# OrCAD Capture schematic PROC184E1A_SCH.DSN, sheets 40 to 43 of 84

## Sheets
40 44. MICRO SDCARD INTERFACE: size C; title: Micro SD CARD INTERFACE; note: PROC184_SCH
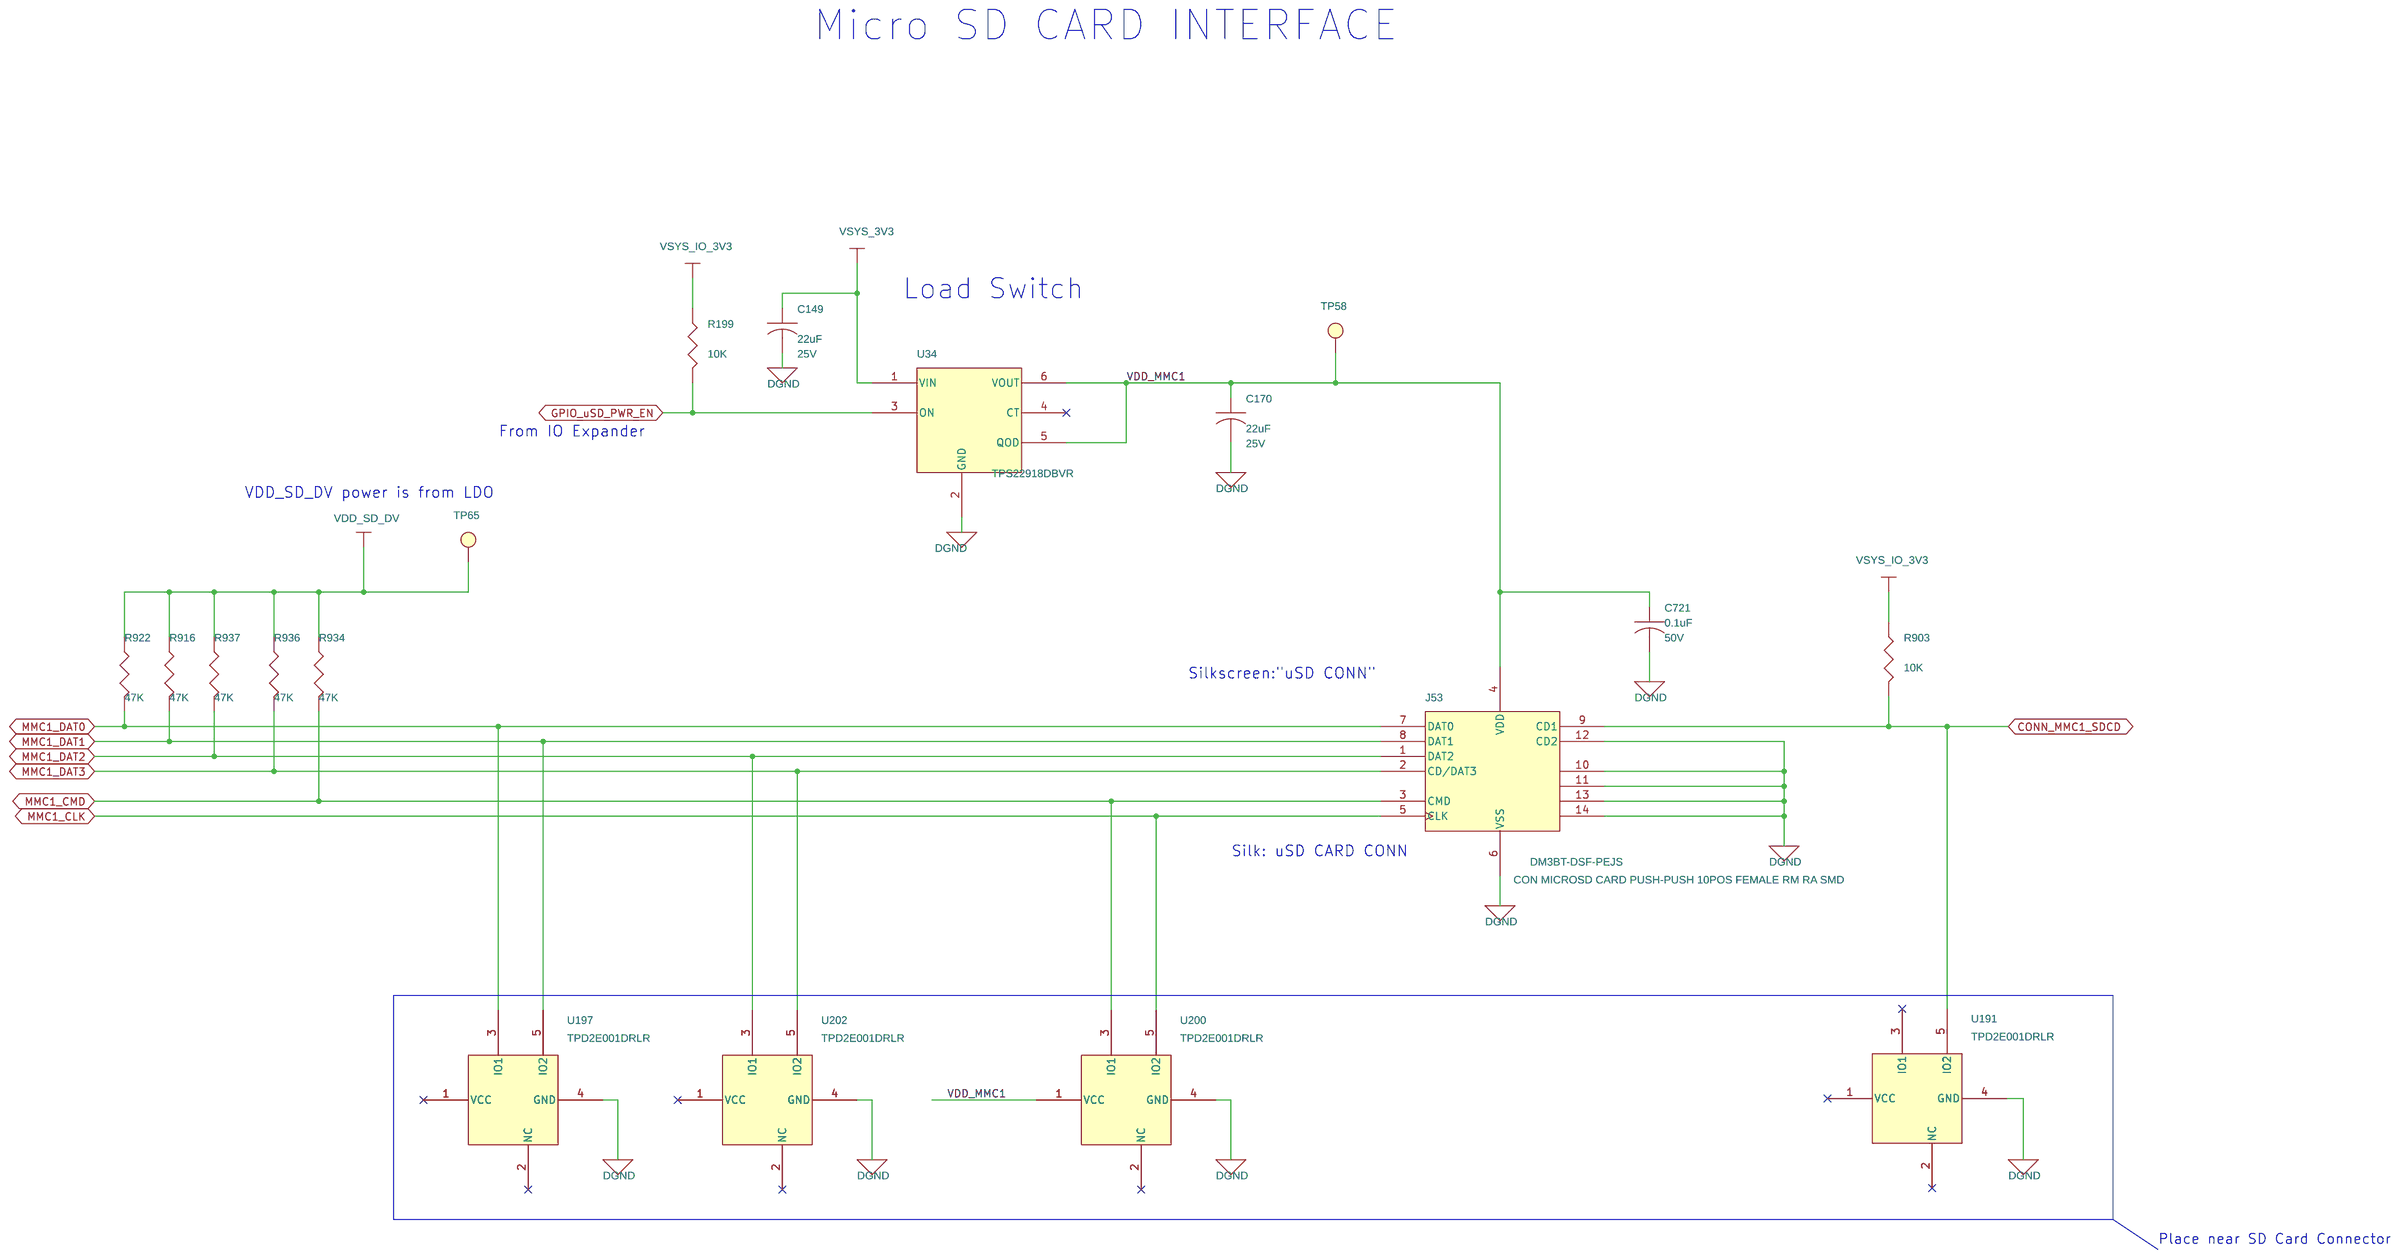
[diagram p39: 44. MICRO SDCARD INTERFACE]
41 45. eMMC FLASH: size C; title: eMMC FLASH; note: PROC184_SCH
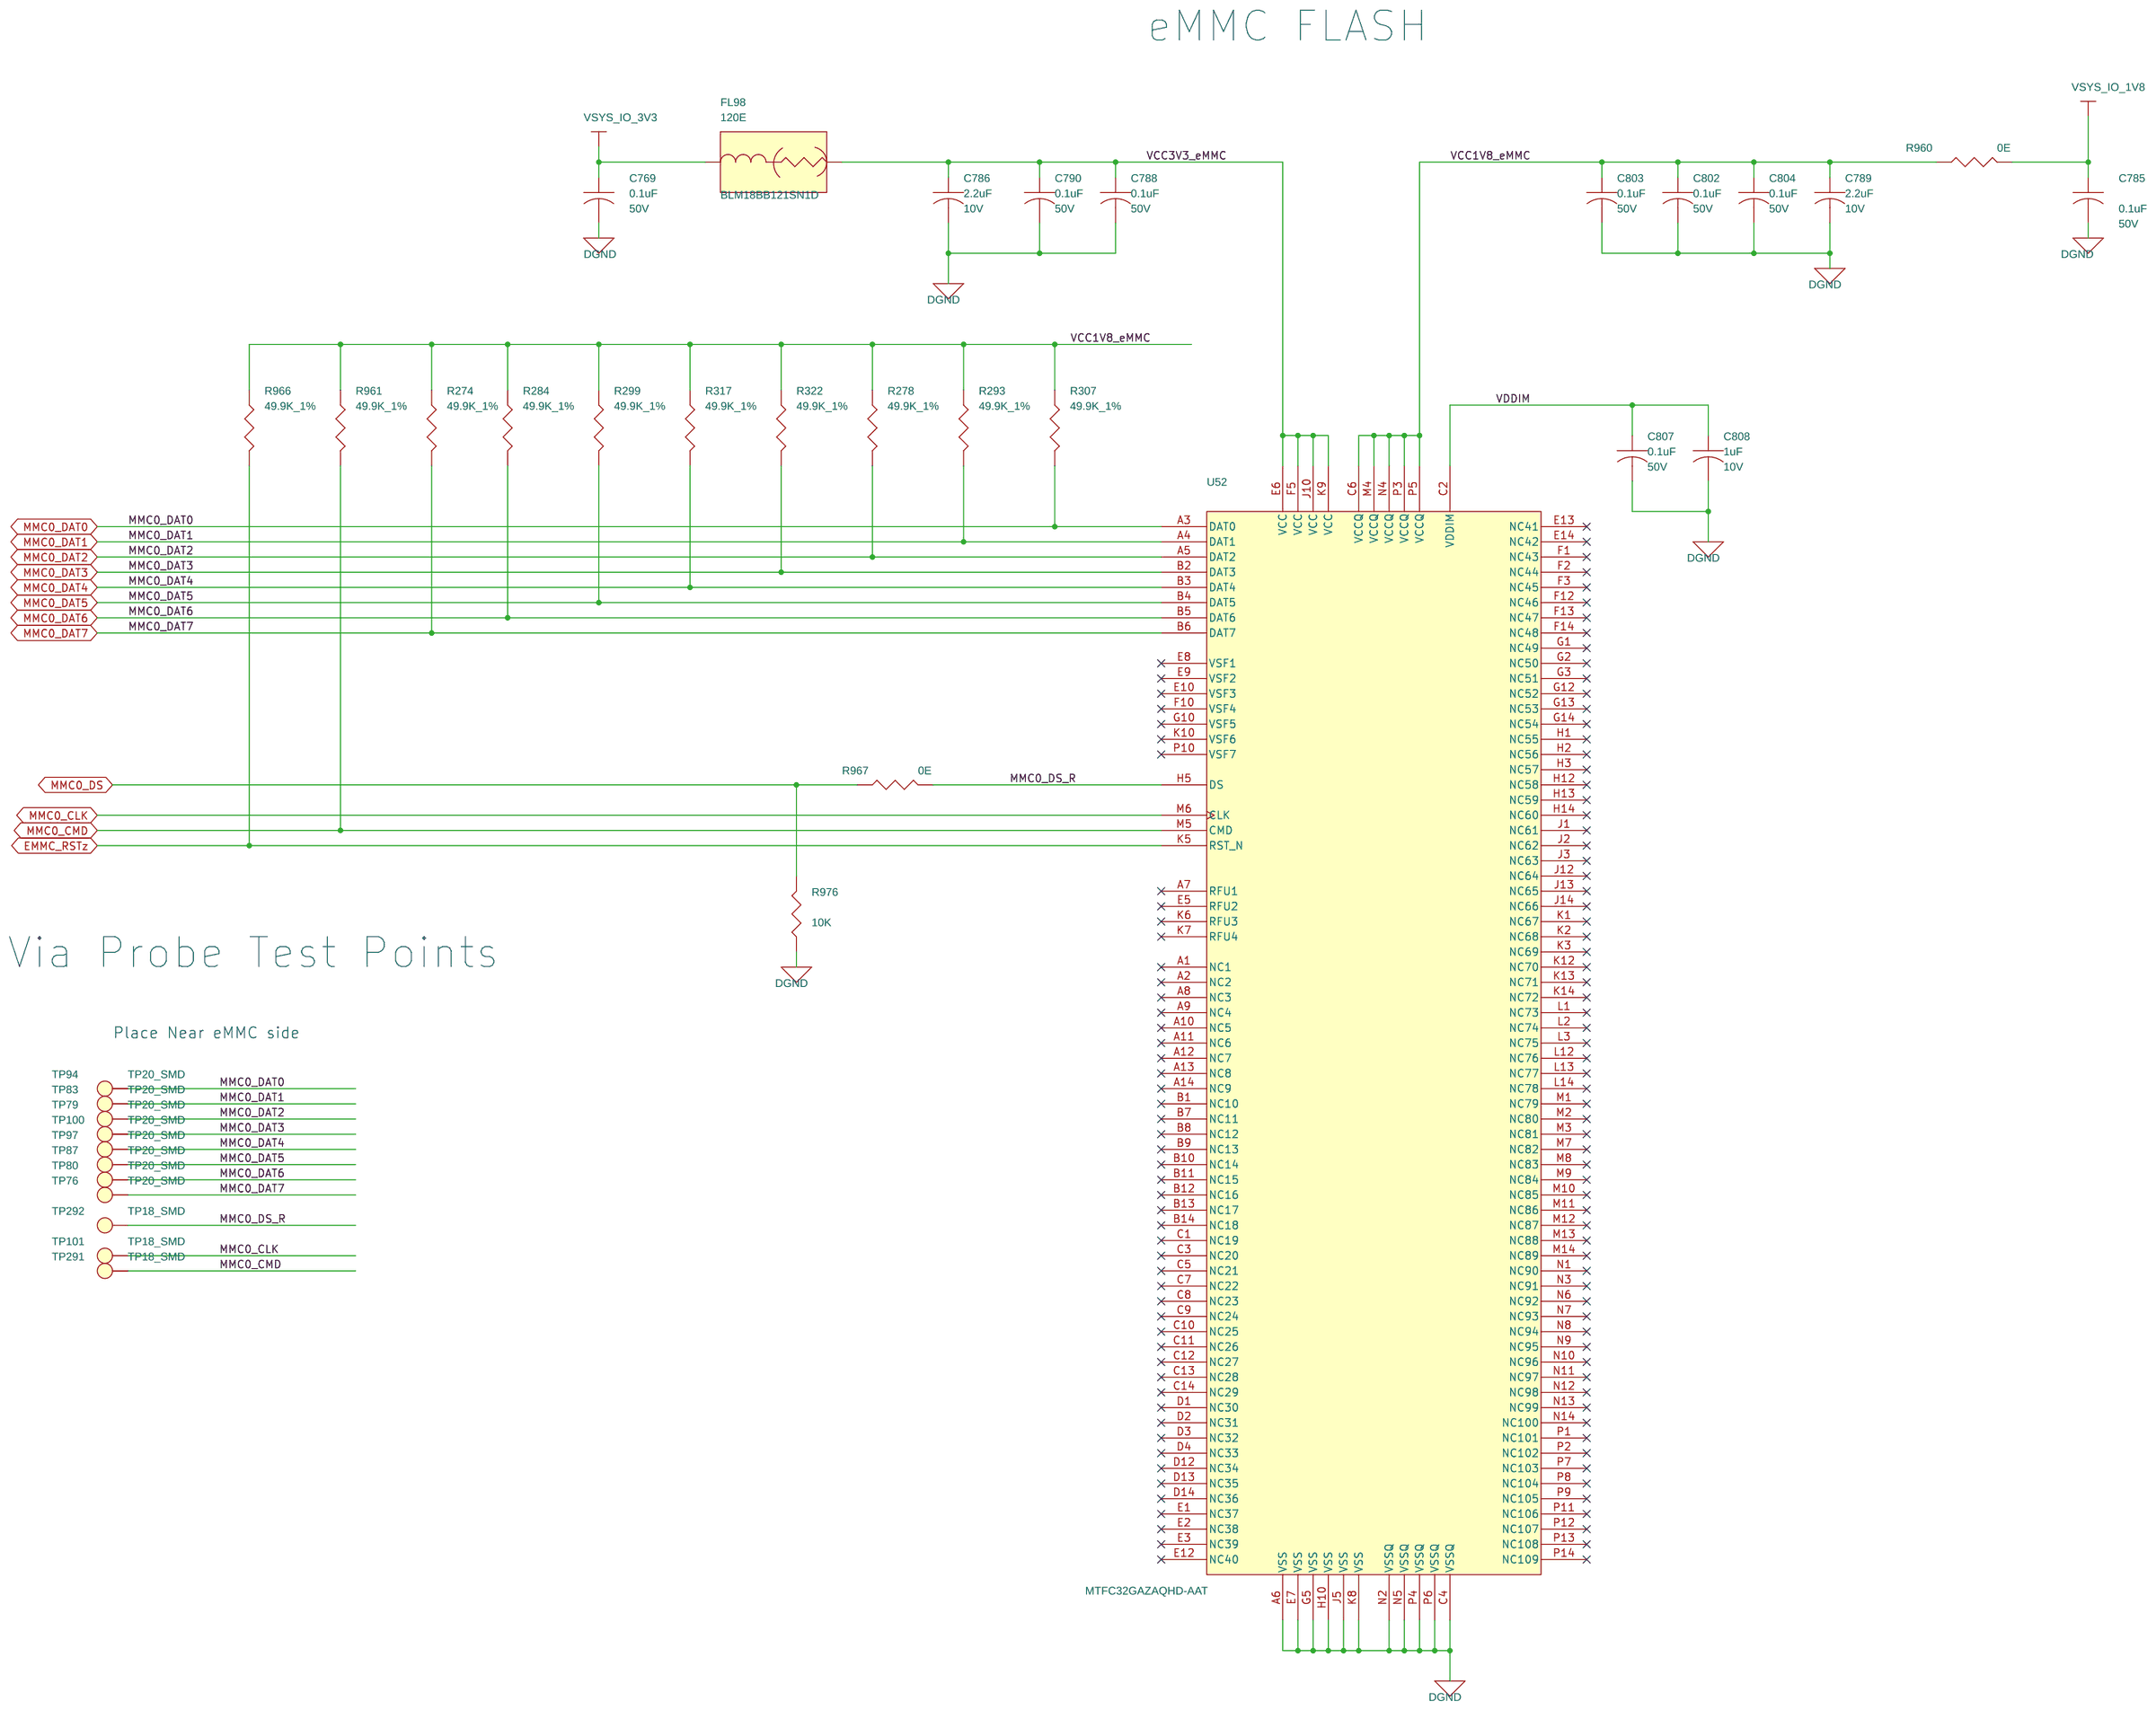
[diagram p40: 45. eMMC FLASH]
42 46. UFS_FLASH: size C; title: UFS FLASH; note: PROC184_SCH
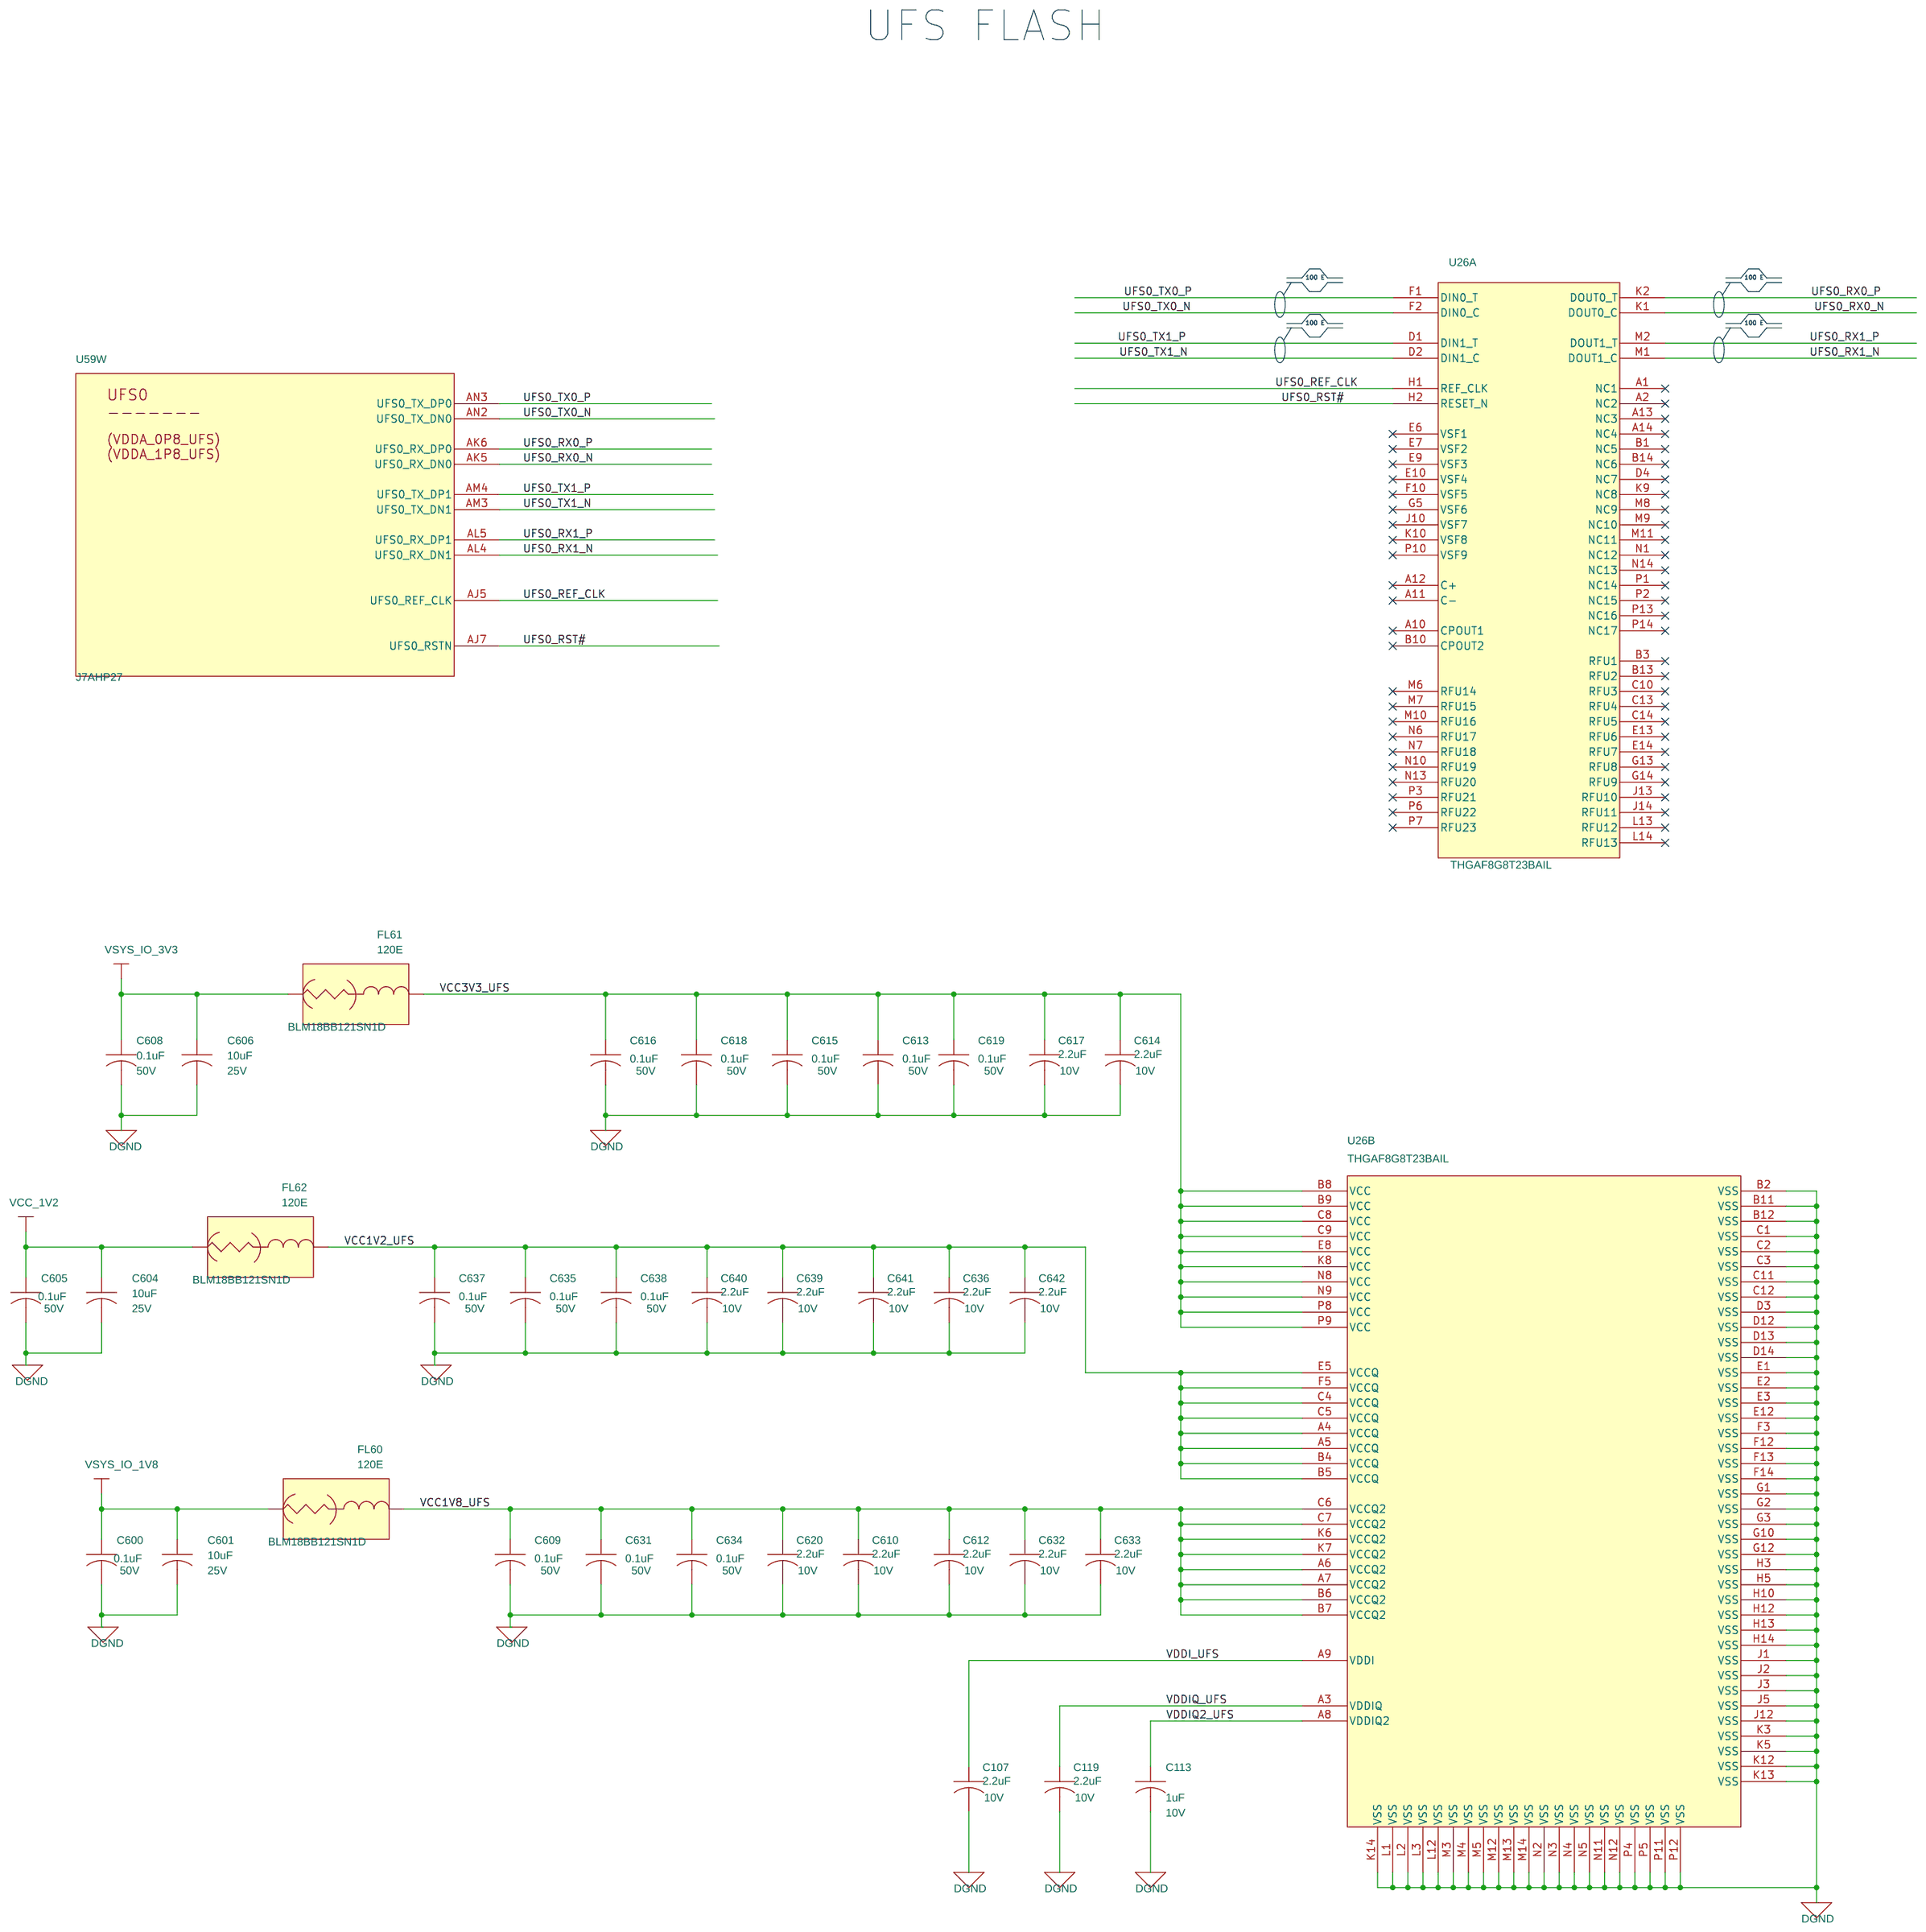
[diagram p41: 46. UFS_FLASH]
43 47. EEPROM: size C; title: EEPROM; note: PROC184_SCH
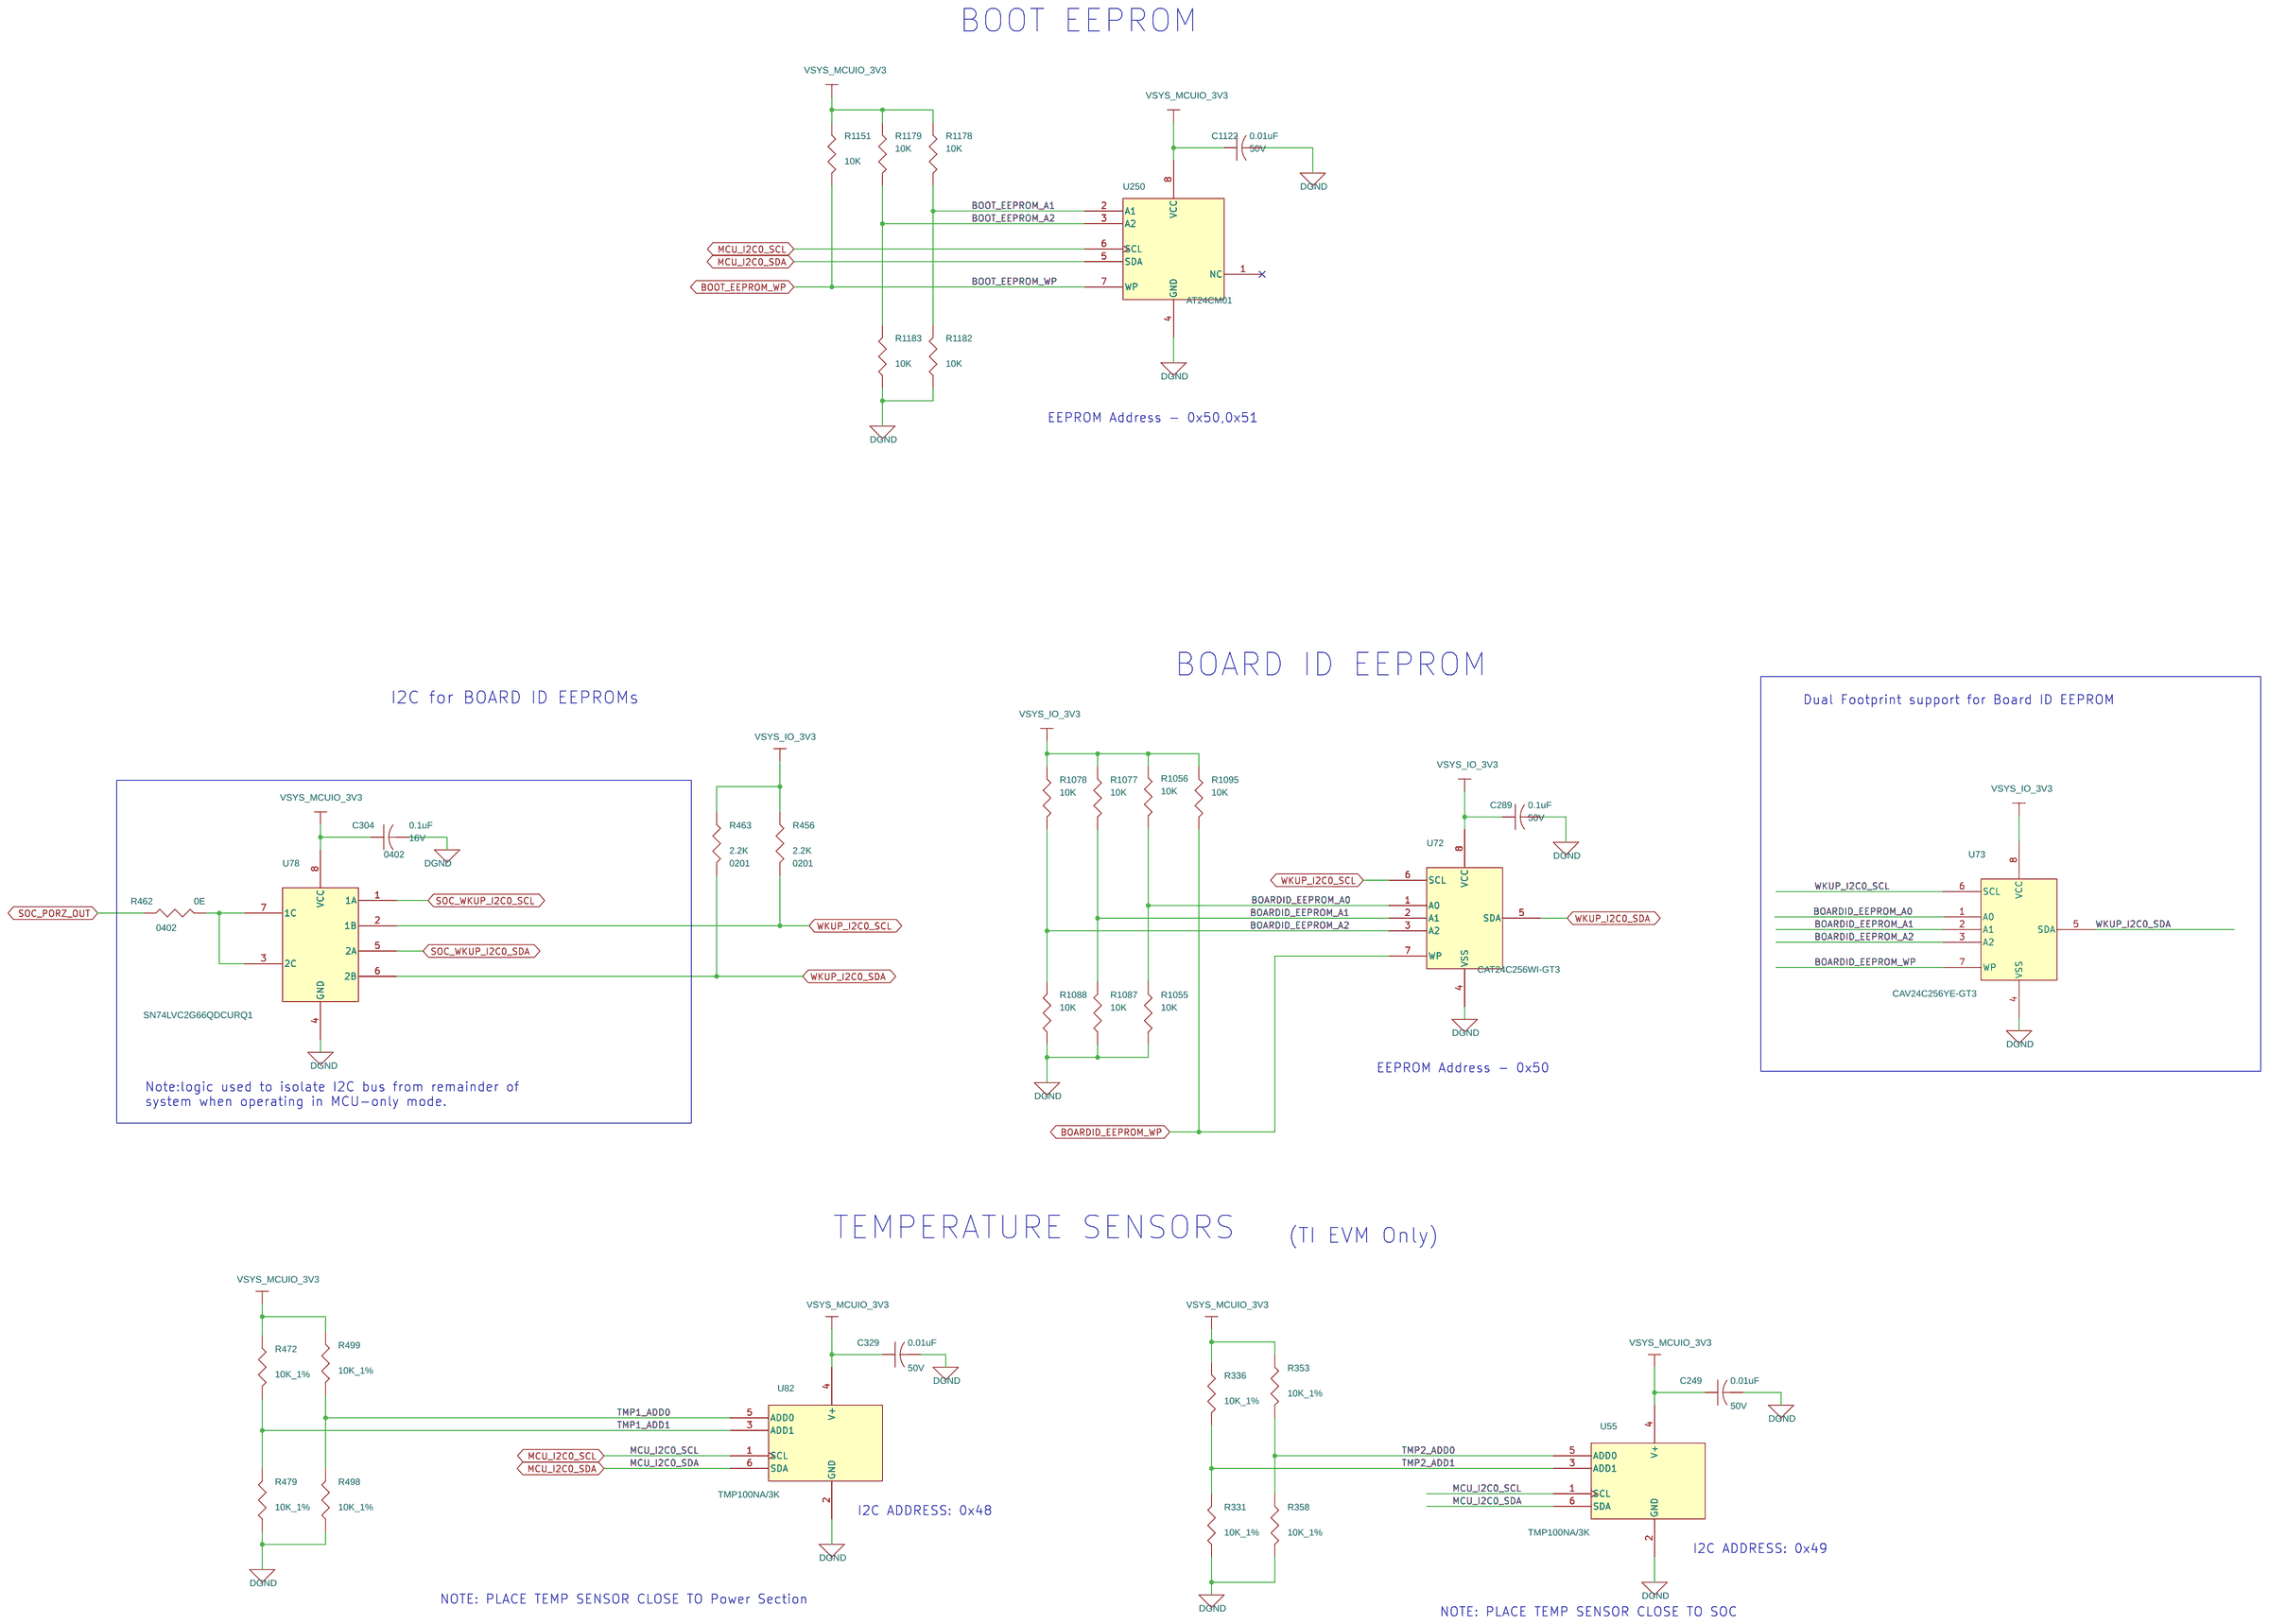
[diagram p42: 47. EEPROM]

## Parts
sheet 15. SOC EMIF1 & LPDDR4
U59  J7AHP27  [BGASKT-33X33-1063-P8MM]  (sections A,B,C,D,E,F,G,H,I,J,K,L,M,N,O,P,Q,R,S,T,U,V,W)
sheet 44. MICRO SDCARD INTERFACE
C149  22uF  [CAP0805_1-5]
C170  22uF  [CAP0805_1-5]
C721  0.1uF  [CAP0402_0-75]
J53  CON_SDCARD10_DM3BT-DSF-PEJS  [CON_SD10_DM3BT-DSF-PEJS_S_R_S_2-4]
R199  10K  [RES0402_0-5]
R903  10K  [RES0402_0-5]
R916  47K  [RES0402_0-5]
R922  47K  [RES0402_0-5]
R934  47K  [RES0402_0-5]
R936  47K  [RES0402_0-5]
R937  47K  [RES0402_0-5]
TP58  TP30_SMD  [TP30_SMD]
TP65  TP30_SMD  [TP30_SMD]
U34  TPS22918DBVR  [SOT23-6]
U191  TPD2E001DRLR  [SOT553-5_0-6]
U197  TPD2E001DRLR  [SOT553-5_0-6]
U200  TPD2E001DRLR  [SOT553-5_0-6]
U202  TPD2E001DRLR  [SOT553-5_0-6]
sheet 45. eMMC FLASH
C769  0.1uF  [CAP0402_0-75]
C785  0.1uF  [CAP0402_0-75]
C786  2.2uF  [CAP0402_0-75]
C788  0.1uF  [CAP0402_0-75]
C789  2.2uF  [CAP0402_0-75]
C790  0.1uF  [CAP0402_0-75]
C802  0.1uF  [CAP0402_0-75]
C803  0.1uF  [CAP0402_0-75]
C804  0.1uF  [CAP0402_0-75]
C807  0.1uF  [CAP0402_0-75]
C808  1uF  [CAP0402_0-75]
FL98  120E  [EMIFIL_BLM18A_0603]
R274  49.9K_1%  [RES0402_0-5]
R278  49.9K_1%  [RES0402_0-5]
R284  49.9K_1%  [RES0402_0-5]
R293  49.9K_1%  [RES0402_0-5]
R299  49.9K_1%  [RES0402_0-5]
R307  49.9K_1%  [RES0402_0-5]
R317  49.9K_1%  [RES0402_0-5]
R322  49.9K_1%  [RES0402_0-5]
R960  0E  [RES0402_0-5]
R961  49.9K_1%  [RES0402_0-5]
R966  49.9K_1%  [RES0402_0-5]
R967  0E  [RES0402_0-5]
R976  10K  [RES0402_0-5]
TP76  TP20_SMD  [TP20_SMD]
TP79  TP20_SMD  [TP20_SMD]
TP80  TP20_SMD  [TP20_SMD]
TP83  TP20_SMD  [TP20_SMD]
TP87  TP20_SMD  [TP20_SMD]
TP94  TP20_SMD  [TP20_SMD]
TP97  TP20_SMD  [TP20_SMD]
TP100  TP20_SMD  [TP20_SMD]
TP101  TP18_SMD  [TP18_SMD]
TP291  TP18_SMD  [TP18_SMD]
TP292  TP18_SMD  [TP18_SMD]
U52  MTFC32GAZAQHD-AAT  [VFBGA153_19-68_460X520_0-9]
sheet 46. UFS_FLASH
C107  2.2uF  [CAP0402_0-75]
C113  1uF  [CAP0402_0-75]
C119  2.2uF  [CAP0402_0-75]
C600  0.1uF  [CAP0402_0-75]
C601  10uF  [CAP0603_1-25]
C604  10uF  [CAP0603_1-25]
C605  0.1uF  [CAP0402_0-75]
C606  10uF  [CAP0603_1-25]
C608  0.1uF  [CAP0402_0-75]
C609  0.1uF  [CAP0402_0-75]
C610  2.2uF  [CAP0402_0-75]
C612  2.2uF  [CAP0402_0-75]
C613  0.1uF  [CAP0402_0-75]
C614  2.2uF  [CAP0402_0-75]
C615  0.1uF  [CAP0402_0-75]
C616  0.1uF  [CAP0402_0-75]
C617  2.2uF  [CAP0402_0-75]
C618  0.1uF  [CAP0402_0-75]
C619  0.1uF  [CAP0402_0-75]
C620  2.2uF  [CAP0402_0-75]
C631  0.1uF  [CAP0402_0-75]
C632  2.2uF  [CAP0402_0-75]
C633  2.2uF  [CAP0402_0-75]
C634  0.1uF  [CAP0402_0-75]
C635  0.1uF  [CAP0402_0-75]
C636  2.2uF  [CAP0402_0-75]
C637  0.1uF  [CAP0402_0-75]
C638  0.1uF  [CAP0402_0-75]
C639  2.2uF  [CAP0402_0-75]
C640  2.2uF  [CAP0402_0-75]
C641  2.2uF  [CAP0402_0-75]
C642  2.2uF  [CAP0402_0-75]
FL60  120E  [EMIFIL_BLM18A_0603]
FL61  120E  [EMIFIL_BLM18A_0603]
FL62  120E  [EMIFIL_BLM18A_0603]
U26  THGAF8G8T23BAIL  [VFBGA153_19-68_460X520_0-8]  (sections A,B)
sheet 47. EEPROM
C249  0.01uF  [CAP0402_0-75]
C289  0.1uF  [CAP0402_0-75]
C304  0.1uF  [CAP0402_0-75]
C329  0.01uF  [CAP0402_0-75]
C1122  0.01uF  [CAP0402_0-75]
R331  10K_1%  [RES0402_0-5]
R336  10K_1%  [RES0402_0-5]
R353  10K_1%  [RES0402_0-5]
R358  10K_1%  [RES0402_0-5]
R456  2.2K  [RES0201_0-5]
R462  0E  [RES0402_0-5]
R463  2.2K  [RES0201_0-5]
R472  10K_1%  [RES0402_0-5]
R479  10K_1%  [RES0402_0-5]
R498  10K_1%  [RES0402_0-5]
R499  10K_1%  [RES0402_0-5]
R1055  10K  [RES0402_0-5]
R1056  10K  [RES0402_0-5]
R1077  10K  [RES0402_0-5]
R1078  10K  [RES0402_0-5]
R1087  10K  [RES0402_0-5]
R1088  10K  [RES0402_0-5]
R1095  10K  [RES0402_0-5]
R1151  10K  [RES0402_0-5]
R1178  10K  [RES0402_0-5]
R1179  10K  [RES0402_0-5]
R1182  10K  [RES0402_0-5]
R1183  10K  [RES0402_0-5]
U55  TMP100NA/3K  [SOT23-6_1-5]
U72  CAT24C256WI-GT3  [SOIC8_1-8]
U73  CAV24C256YE-GT3  [TSSOP8_25-59_125X180_1-2]
U78  SN74LVC2G66QDCURQ1  [VSSOP8_19-68_85X95_0-9]
U82  TMP100NA/3K  [SOT23-6_1-5]
U250  AT24CM01  [TSSOP8_25-59_125X180_1-2]

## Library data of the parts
U59 = J7AHP27SoC_BGA1063: IC J7AHP27 SoC EVM MICROPROCESSOR BGA1063; Chkd/date: PRADEEP/181223; Crtd /date: TAMILARASU/111223; Custom_Duty: 15%; Customs_HS_Code: 85423100; Distributor_name: NA; Distributor_part_number: NA; Footprint Path: Y:\MIS_DATABASE\Library\ALTIUM_TOOL\PCB_FOOTPRINTS\Altium_Footprint_Lib.PcbLib; Height: 3.30MM; Library Path: Y:\MIS_DATABASE\Library\ALTIUM_TOOL\SCHEMATICS_PARTS\MS_MICROPROCESSOR_Library.schlib; Mfr_name: NA; Mistral Part No: 141223120002; Package: BGA1063; Part_type: ICS\DIGITAL\MICROPROCESSOR; Project: J7AHP27_V08 SOC; RoHS: NA; Temperature: NA; Tolerance: NA; Voltage: NA; Wattage: NA; Weight: NA; Datasheet: Y:\MIS_DATABASE\DATASHEETS\ICS\DIGITAL\MICROCONTROLLER\J7AHP27.PDF
C149 C170 = CAP: CAP CERAMIC 22uF 25V 20% X5R 0805; Automotive Alternate_mfr_name: MURATA; Automotive Alternate_mfr_part_number: GRT21BR61E226ME13L; Chkd/date: USMAN/191213; Crtd /date: USMAN/191213; Custom_Duty: 15%; Customs_HS_Code: 85322990; Direct Alternate_mfr_name: MURATA; Direct Alternate_mfr_part_number: GRM21BR61E226ME44L; Distributor_name: DIGIKEY; Distributor_part_number: 1276-2908-1-ND; Footprint Path: Y:\MIS_DATABASE\Library\ALTIUM_TOOL\PCB_FOOTPRINTS\Altium_Footprint_Lib.PcbLib; Height: 1.40MM; Library Path: Y:\MIS_DATABASE\Library\ALTIUM_TOOL\SCHEMATICS_PARTS\MS_DISCRETE_Library.schlib; Manufacturer: SAMSUNG; Mfr_name: SAMSUNG; Mfr_part_number: CL21A226MAQNNNE; Mistral Part No: 120013120018-R; Package: 0805; Part_type: CAPACITORS\CERAMIC; Project: ITS2_RF; RoHS: RoHS; Temperature: -55°C+85°C; Tolerance: 20%; Voltage: 25V; Wattage: NA; Weight: 5.5mg; Datasheet: Y:\MIS_DATABASE\DATASHEETS\CAPACITORS\CL_SERIES.PDF
C289 C600 C605 C608 C609 C613 C615 C616 C618 C619 C631 C634 C635 C637 C638 C721 C769 C785 C788 C790 C802-C804 C807 = CAP: CAP CERAMIC 0.1uF 50V 10% X7R 0402; Automotive Alternate_mfr_name: TDK; Automotive Alternate_mfr_part_number: CGA2B3X7R1H104K050BB; Chkd/date: MANIRAJA/261020; Crtd /date: ALVY/211020; Custom_Duty: 15%; Customs_HS_Code: 85322990; Direct Alternate_mfr_name: TDK; Direct Alternate_mfr_part_number: C1005X7R1H104K050BE; Distributor_name: DIGIKEY; Distributor_part_number: 490-10700-1-ND; Footprint Path: Y:\MIS_DATABASE\Library\ALTIUM_TOOL\PCB_FOOTPRINTS\Altium_Footprint_Lib.PcbLib; Height: 0.55MM; Library Path: Y:\MIS_DATABASE\Library\ALTIUM_TOOL\SCHEMATICS_PARTS\MS_DISCRETE_Library.schlib; Manufacturer: MURATA; Mfr_name: MURATA; Mfr_part_number: GRM155R71H104KE14D; Mistral Part No: 120011100014-R; Package: 0402; Part_type: CAPACITORS\CERAMIC; Project: J7_CP; RoHS: RoHS; Temperature: -55°C+125°C; Tolerance: 10%; Voltage: 50V; Wattage: NA; Weight: 3.1mg; Datasheet: Y:\MIS_DATABASE\DATASHEETS\CAPACITORS\GRM155R71H104KE14.PDF
J53 = CON_SDCARD_10_DM3BT-DSF-PEJS: CON MICROSD CARD PUSH-PUSH 10POS FEMALE RM RA SMD; Chkd/date: MANIRAJA/080218; Crtd /date: BAVISH/190111; Custom_Duty: 24%; Customs_HS_Code: 85369090; Distributor_name: DIGIKEY; Distributor_part_number: HR1942CT-ND; Footprint Path: Y:\MIS_DATABASE\Library\ALTIUM_TOOL\PCB_FOOTPRINTS\Altium_Footprint_Lib.PcbLib; Height: 2.38MM; Library Path: Y:\MIS_DATABASE\Library\ALTIUM_TOOL\SCHEMATICS_PARTS\MS_CONNECTOR_Library.schlib; Manufacturer: HIROSE ELECTRIC; Mfr_name: HIROSE ELECTRIC; Mfr_part_number: DM3BT-DSF-PEJS; Mistral Part No: 150011010020-R; Package: SMD; Part_type: CONNECTOR\MEMORY CARD; Project: EBOOK; RoHS: RoHS; Temperature: -25°C+85°C; Tolerance: NA; Voltage: NA; Wattage: NA; Weight: 1.315g; Datasheet: Y:\MIS_DATABASE\DATASHEETS\CONNECTORS\DM3-SERIES.PDF
R199 R903 R976 R1056 R1087 R1088 R1151 R1182 R1183 = RESISTOR: RES 10K 1/16W 5% 0402; Chkd/date: VASANTHA/061216; Crtd /date: MAZHAR/230805; Custom_Duty: 15%; Customs_HS_Code: 85332119; Distributor_name: DIGIKEY; Distributor_part_number: 311-10KJRCT-ND; Footprint Path: Y:\MIS_DATABASE\Library\ALTIUM_TOOL\PCB_FOOTPRINTS\Altium_Footprint_Lib.PcbLib; Height: 0.40MM; Library Path: Y:\MIS_DATABASE\Library\ALTIUM_TOOL\SCHEMATICS_PARTS\MS_DISCRETE_Library.schlib; Manufacturer: YAGEO AMERICA; Mfr_name: YAGEO AMERICA; Mfr_part_number: RC0402JR-0710KL; Mistral Part No: 110011060021-R; Package: 0402; Part_type: RESISTORS\FIXED; Project: HSE; RoHS: RoHS; Temperature: -55°C+155°C; Tolerance: 5%; Voltage: NA; Wattage: 1/16W; Weight: 0.65mg; Datasheet: Y:\MIS_DATABASE\DATASHEETS\RESISTORS\RCXXXXL-SER_MAR18.PDF
R916 R922 R934 R936 R937 = RESISTOR: RES 47K 1/10W 5% 0402; Chkd/date: VASANTHA/281216; Crtd /date: MAZHAR/120505; Custom_Duty: 15%; Customs_HS_Code: 85332119; Distributor_name: DIGIKEY; Distributor_part_number: P47KJCT-ND; Footprint Path: Y:\MIS_DATABASE\Library\ALTIUM_TOOL\PCB_FOOTPRINTS\Altium_Footprint_Lib.PcbLib; Height: 0.40MM; Library Path: Y:\MIS_DATABASE\Library\ALTIUM_TOOL\SCHEMATICS_PARTS\MS_DISCRETE_Library.schlib; Manufacturer: PANASONIC-ECG; Mfr_name: PANASONIC-ECG; Mfr_part_number: ERJ-2GEJ473X; Mistral Part No: 110009030882-R; Package: 0402; Part_type: RESISTORS\FIXED; Project: CTP02_REVA_BASE; RoHS: RoHS; Temperature: -55°C+155°C; Tolerance: 5%; Voltage: NA; Wattage: 1/10W; Weight: 0.8mg; Datasheet: Y:\MIS_DATABASE\DATASHEETS\RESISTORS\PAN-ERJSER_NOV17.PDF
TP58 TP65 = TESTPOINT: TESTPOINT CIR 30 SMD; Chkd/date: SHREESHAIL/171006; Crtd /date: MAZHAR/171006; Custom_Duty: NA; Customs_HS_Code: NA; Distributor_name: NA; Distributor_part_number: NA; Footprint Path: Y:\MIS_DATABASE\Library\ALTIUM_TOOL\PCB_FOOTPRINTS\Altium_Footprint_Lib.PcbLib; Height: NA; Library Path: Y:\MIS_DATABASE\Library\ALTIUM_TOOL\SCHEMATICS_PARTS\MS_DISCRETE_Library.schlib; MECHANICAL 3D STEP FILE: NA; Manufacturer: LOCAL; Mfr_name: LOCAL; Mistral Part No: 130009030930; Package: SMD; Project: BT MODULE_CSRBC04; RoHS: NA; Temperature: NA; Tolerance: NA; Voltage: NA; Wattage: NA; Weight: NA; Datasheet: NA
U34 = TPS22918DBVR_SOT23-6: IC ON RESISTANCE LOAD SWITCH SOT23-6; Automotive Alternate_mfr_name: TEXAS INSTRUMENTS; Automotive Alternate_mfr_part_number: TPS22918TDBVRQ1; Chkd/date: VASANTHA/130516; Crtd /date: VASANTHA/130516; Custom_Duty: 15%; Customs_HS_Code: 85423100; Distributor_name: DIGIKEY; Distributor_part_number: TPS22918DBVR-ND; Height: 1.45MM; Manufacturer: TEXAS INSTRUMENTS; Mfr_name: TEXAS INSTRUMENTS; Mistral Part No: 142016050007-R; Part_type: ICS\POWER; Project: TMDXCSK8127; RoHS: RoHS; Temperature: -40°C to 105°C; Tolerance: NA; Voltage: NA; Wattage: NA; Weight: NA; Datasheet: Y:\MIS_DATABASE\DATASHEETS\ICS\POWER\TPS22918DBV.PDF
U191 U197 U202 = TPD2E001DRLR_SOT-5_1: IC ESD-PROTECTION DIODE ARRAYS SOT-5; Automotive Alternate_mfr_name: TEXAS INSTRUMENTS; Automotive Alternate_mfr_part_number: TPD2E001IDRLRQ1; Chkd/date: NAVEED/150714; Crtd /date: MUDDU/250510; Custom_Duty: 15%; Customs_HS_Code: 85423100; Distributor_name: DIGIKEY; Distributor_part_number: 296-21883-1-ND; Footprint Path: Y:\MIS_DATABASE\Library\ALTIUM_TOOL\PCB_FOOTPRINTS\Altium_Footprint_Lib.PcbLib; Height: 0.60MM; Library Path: Y:\MIS_DATABASE\Library\ALTIUM_TOOL\SCHEMATICS_PARTS\MS_FILTER_Library.schlib; Library Ref: TPD2E001DRLR_SOT-5; Mfr_name: TEXAS INSTRUMENTS; Mistral Part No: 140110060007-R; Package: SOT-5; Part_type: ICS\ANALOG\ACTIVE FILTER; Project: CENTAURUS; RoHS: RoHS; Temperature: -40°C+85°C; Tolerance: NA; Voltage: NA; Wattage: NA; Weight: 2.8mg; Datasheet: Y:\MIS_DATABASE\DATASHEETS\ICS\MISC\TPD2E001DRLR.PDF
U200 = TPD2E001DRLR_SOT-5: IC ESD-PROTECTION DIODE ARRAYS SOT-5; Chkd/date: NAVEED/150714; Crtd /date: MUDDU/250510; Custom_Duty: 15%; Customs_HS_Code: 85423100; Distributor_name: DIGIKEY; Distributor_part_number: 296-21883-1-ND; Footprint Path: Y:\MIS_DATABASE\Library\ALTIUM_TOOL\PCB_FOOTPRINTS\Altium_Footprint_Lib.PcbLib; Height: 0.60MM; Library Path: Y:\MIS_DATABASE\Library\ALTIUM_TOOL\SCHEMATICS_PARTS\MS_FILTER_Library.schlib; Manufacturer: TEXAS INSTRUMENTS; Mfr_name: TEXAS INSTRUMENTS; Mistral Part No: 140110060007-R; Package: SOT-5; Part_type: ICS\ANALOG\ACTIVE FILTER; Project: CENTAURUS; RoHS: RoHS; Temperature: -40°C+85°C; Tolerance: NA; Voltage: NA; Wattage: NA; Weight: 2.8mg; Datasheet: Y:\MIS_DATABASE\DATASHEETS\ICS\MISC\TPD2E001DRLR.PDF
C610 C612 C614 C617 C620 C632 C633 C636 C639-C642 C786 C789 = CAP: CAP CERAMIC 2.2uF 10V 10% X5R 0402; Automotive Alternate_mfr_name: TAIYO YUDEN; Automotive Alternate_mfr_part_number: LMK105ABJ225MVHF; Chkd/date: MANIRAJA/251120; Crtd /date: ALVY/241120; Custom_Duty: 15%; Customs_HS_Code: 85322990; Direct Alternate_mfr_name: TDK; Direct Alternate_mfr_part_number: C1005X5R1A225K050BC; Distributor_name: MOUSER; Distributor_part_number: 81-GRM155R61A225K01D; Footprint Path: Y:\MIS_DATABASE\Library\ALTIUM_TOOL\PCB_FOOTPRINTS\Altium_Footprint_Lib.PcbLib; Height: 0.55MM; Library Path: Y:\MIS_DATABASE\Library\ALTIUM_TOOL\SCHEMATICS_PARTS\MS_DISCRETE_Library.schlib; Manufacturer: MURATA; Mfr_name: MURATA; Mfr_part_number: GRM155R61A225KE01D; Mistral Part No: 120011100038-R; Package: 0402; Part_type: CAPACITORS\CERAMIC; Project: PLCC_DIGITAL BRD PROTO; RoHS: RoHS; Temperature: -55°C+85°C; Tolerance: 10%; Voltage: 10V; Wattage: NA; Weight: 1.6mg; Datasheet: Y:\MIS_DATABASE\DATASHEETS\CAPACITORS\MURATA-GXX-SER_NOV17.PDF
C113 C808 = CAP: CAP CERAMIC 1uF 10V 10% X7S AUTO 0402; Automotive Alternate_mfr_name: TAIYO YUDEN; Automotive Alternate_mfr_part_number: EMK105BJ105KVHF; Chkd/date: MANIRAJA/100918; Crtd /date: ALVY/100918; Custom_Duty: 15%; Customs_HS_Code: 85322990; Direct Alternate_mfr_name: YAGEO AMERICA; Direct Alternate_mfr_part_number: CC0402KRX5R7BB105; Distributor_name: DIGIKEY; Distributor_part_number: 490-13409-1-ND; Footprint Path: Y:\MIS_DATABASE\Library\ALTIUM_TOOL\PCB_FOOTPRINTS\Altium_Footprint_Lib.PcbLib; Height: 0.70MM; Library Path: Y:\MIS_DATABASE\Library\ALTIUM_TOOL\SCHEMATICS_PARTS\MS_DISCRETE_Library.schlib; Manufacturer: TDK CORPORATION; Mfr_name: MURATA; Mfr_part_number: GCM155C71A105KE38D; Mistral Part No: 120018090021-R; Package: 0402; Part_type: CAPACITORS\CERAMIC; Project: SMART-M_SCRIPTALK_PB; RoHS: RoHS; Temperature: -55°C+125°C; Tolerance: 10%; Voltage: 10V; Wattage: NA; Weight: 6mg; Datasheet: Y:\MIS_DATABASE\DATASHEETS\CAPACITORS\MURATA-GCM-SER.PDF
FL60-FL62 FL98 = EMIFILTER_IND: PASSIVE FILTER EMI 120E 0603; Automotive Alternate_mfr_name: TDK; Automotive Alternate_mfr_part_number: MMZ1608D121BTD25; Chkd/date: MAZHAR/030809; Crtd /date: USMAN/070109; Custom_Duty: 24%; Customs_HS_Code: 85437099; Direct Alternate_mfr_name: TDK; Direct Alternate_mfr_part_number: MMZ1608D121BTA00; Distributor_name: DIGIKEY; Distributor_part_number: 490-1020-1-ND; Height: 0.95MM; Manufacturer: MURATA; Mfr_name: MURATA; Mfr_part_number: BLM18BB121SN1D; Mistral Part No: 130009030758; Package: 0603; Part_type: FILTER; Project: OMAP_EVM; Datasheet: Y:\MIS_DATABASE\DATASHEETS\ICS\MISC\BLM18B.PDF
R274 R278 R284 R293 R299 R307 R317 R322 R961 R966 = RESISTOR: RES 49.9K 1/16W 1% 0402; Chkd/date: MAZHAR/220709; Crtd /date: GEETHA/090606; Custom_Duty: 15%; Customs_HS_Code: 85332119; Distributor_name: DIGIKEY; Distributor_part_number: 311-49.9KLRCT-ND; Footprint Path: Y:\MIS_DATABASE\Library\ALTIUM_TOOL\PCB_FOOTPRINTS\Altium_Footprint_Lib.PcbLib; Height: 0.40MM; Library Path: Y:\MIS_DATABASE\Library\ALTIUM_TOOL\SCHEMATICS_PARTS\MS_DISCRETE_Library.schlib; Manufacturer: YAGEO AMERICA; Mfr_name: YAGEO AMERICA; Mfr_part_number: RC0402FR-0749K9L; Mistral Part No: 110009030902-R; Package: 0402; Part_type: RESISTORS\FIXED; Project: PNAV; RoHS: RoHS; Temperature: -55°C+155°C; Tolerance: 1%; Voltage: NA; Wattage: 1/16W; Weight: 0.65mg; Datasheet: Y:\MIS_DATABASE\DATASHEETS\RESISTORS\RCXXXXL-SER_MAR18.PDF
R462 R960 R967 = RESISTOR: RES 0E 1/10W JUMPER 0402; Chkd/date: VASANTHA/061216; Crtd /date: NAVEED/201014; Custom_Duty: 15%; Customs_HS_Code: 85332119; Distributor_name: DIGIKEY; Distributor_part_number: P0.0JCT-ND; Footprint Path: Y:\MIS_DATABASE\Library\ALTIUM_TOOL\PCB_FOOTPRINTS\Altium_Footprint_Lib.PcbLib; Height: 0.40MM; IBISSP_MODLES: VALUE REPEATING 2 TIME; Library Path: Y:\MIS_DATABASE\Library\ALTIUM_TOOL\SCHEMATICS_PARTS\MS_DISCRETE_Library.schlib; Manufacturer: PANASONIC-ECG; Mfr_name: PANASONIC-ECG; Mfr_part_number: ERJ-2GE0R00X; Mistral Part No: 110018030052-R; Package: 0402; Part_type: RESISTORS\FIXED; Project: AEGIS POM; RoHS: RoHS; Temperature: -55°C+155°C; Tolerance: NA; Voltage: NA; Wattage: 1/10W; Weight: 0.8mg; Datasheet: Y:\MIS_DATABASE\DATASHEETS\RESISTORS\PAN-ERJSER_NOV17.PDF
TP76 TP79 TP80 TP83 TP87 TP94 TP97 TP100 = TESTPOINT: TESTPOINT CIR 20 SMD; Chkd/date: SHREESHAIL/171006; Crtd /date: MAZHAR/171006; Custom_Duty: NA; Customs_HS_Code: NA; Distributor_name: NA; Distributor_part_number: NA; Footprint Path: Y:\MIS_DATABASE\Library\ALTIUM_TOOL\PCB_FOOTPRINTS\Altium_Footprint_Lib.PcbLib; Height: NA; Library Path: Y:\MIS_DATABASE\Library\ALTIUM_TOOL\SCHEMATICS_PARTS\MS_DISCRETE_Library.schlib; MECHANICAL 3D STEP FILE: NA; Manufacturer: LOCAL; Mfr_name: LOCAL; Mistral Part No: NA; Package: SMD; Project: BT MODULE_CSRBC04; RoHS: NA; Temperature: NA; Tolerance: NA; Voltage: NA; Wattage: NA; Weight: NA; Datasheet: NA
TP101 TP291 TP292 = TESTPOINT: TESTPOINT 18 SMD; Chkd/date: VASANTHA/120318; Crtd /date: VASANTHA/120318; Distributor_name: NA; Distributor_part_number: NA; Height: NA; Manufacturer: LOCAL; Mfr_name: LOCAL; Mistral Part No: NA; Package: SMD; Project: TI_SVB_MAXWELL_DUT; Temperature: NA; Tolerance: NA; Voltage: NA; Wattage: NA; Weight: NA; Datasheet: NA
U52 = MTFC16GAPALBH_TFBGA153: IC 32GB e-MMC MEMORY VFBGA153; Chkd/date: PRAVEEN/010922; Crtd /date: PRAVEEN/010922; Custom_Duty: 15%; Customs_HS_Code: 85423100; Distributor_name: MOUSER; Distributor_part_number: 340-505567-TRAY; Footprint Path: Y:\MIS_DATABASE\Library\ALTIUM_TOOL\PCB_FOOTPRINTS\Altium_Footprint_Lib.PcbLib; Height: 0.90MM; Library Path: Y:\MIS_DATABASE\Library\ALTIUM_TOOL\SCHEMATICS_PARTS\MS_MISCMEMORY_Library.schlib; Manufacturer: MICRON; Mfr_name: MICRON; Mistral Part No: 141122090007-R; Package: VFBGA153; Part_type: ICS\DIGITAL\MEMORY; Project: J7ES_EVM_FUSION2_BRD; RoHS: RoHS; Temperature: -40°C+105°C; Tolerance: NA; Voltage: NA; Wattage: NA; Weight: NA; Datasheet: Y:\MIS_DATABASE\DATASHEETS\ICS\MEMORY\MTFC32GAZAQHD-AATT.PDF
C107 C119 = CAP: CAP CERAMIC 2.2uF 10V 10% X5R 0402; Assembly_Instruction: DNI; Automotive Alternate_mfr_name: TAIYO YUDEN; Automotive Alternate_mfr_part_number: LMK105ABJ225MVHF; Chkd/date: MANIRAJA/251120; Crtd /date: ALVY/241120; Custom_Duty: 15%; Customs_HS_Code: 85322990; Direct Alternate_mfr_name: TDK; Direct Alternate_mfr_part_number: C1005X5R1A225K050BC; Distributor_name: MOUSER; Distributor_part_number: 81-GRM155R61A225K01D; Footprint Path: Y:\MIS_DATABASE\Library\ALTIUM_TOOL\PCB_FOOTPRINTS\Altium_Footprint_Lib.PcbLib; Height: 0.55MM; Library Path: Y:\MIS_DATABASE\Library\ALTIUM_TOOL\SCHEMATICS_PARTS\MS_DISCRETE_Library.schlib; Manufacturer: MURATA; Mfr_name: MURATA; Mfr_part_number: GRM155R61A225KE01D; Mistral Part No: 120011100038-R; Package: 0402; Part_type: CAPACITORS\CERAMIC; Project: PLCC_DIGITAL BRD PROTO; RoHS: RoHS; Temperature: -55°C+85°C; Tolerance: 10%; Voltage: 10V; Wattage: NA; Weight: 1.6mg; Datasheet: Y:\MIS_DATABASE\DATASHEETS\CAPACITORS\MURATA-GXX-SER_NOV17.PDF
C601 C604 C606 = CAP: CAP CERAMIC 10uF 25V 20% X5R 0603; Automotive Alternate_mfr_name: MURATA; Automotive Alternate_mfr_part_number: GRT188R61E106ME13D; Chkd/date: MANIRAJA/040718; Crtd /date: MANIRAJA/040718; Custom_Duty: 15%; Customs_HS_Code: 85322990; Direct Alternate_mfr_name: TDK; Direct Alternate_mfr_part_number: C1608X5R1E106M080AC; Distributor_name: DIGIKEY; Distributor_part_number: 490-10991-1-ND; Footprint Path: Y:\MIS_DATABASE\Library\ALTIUM_TOOL\PCB_FOOTPRINTS\Altium_Footprint_Lib.PcbLib; Height: 1.20MM; Library Path: Y:\MIS_DATABASE\Library\ALTIUM_TOOL\SCHEMATICS_PARTS\MS_DISCRETE_Library.schlib; Manufacturer: MURATA; Mfr_name: MURATA; Mfr_part_number: ZRB18AR61E106ME01L; Mistral Part No: 120018070001-R; Package: 0603; Part_type: CAPACITORS\CERAMIC; Project: CABS_VME_DIO; RoHS: RoHS; Temperature: -55°C+85°C; Tolerance: 20%; Voltage: 25V; Wattage: NA; Weight: 2mg; Datasheet: Y:\MIS_DATABASE\DATASHEETS\CAPACITORS\ZRB18AR61E106ME01L.PDF
U26 = THGAF4G9N4LBAIR_VFBGA153: IC 32GB NAND FLASH UFS MEMORY PWFBGA153; Chkd/date: MANIRAJA/220518; Crtd /date: MANIRAJA/220518; Custom_Duty: 15%; Customs_HS_Code: 85423100; Distributor_name: DIGIKEY; Distributor_part_number: THGAF8G8T23BAIL-ND; Footprint Path: Y:\MIS_DATABASE\Library\ALTIUM_TOOL\PCB_FOOTPRINTS\Altium_Footprint_Lib.PcbLib; Height: 0.80MM; Library Path: Y:\MIS_DATABASE\Library\ALTIUM_TOOL\SCHEMATICS_PARTS\MS_MISCMEMORY_Library.schlib; Manufacturer: TOSHIBA; Mfr_name: TOSHIBA; Mistral Part No: 141118050003-R; Package: PWFBGA153; Part_type: ICS\DIGITAL\MEMORY; Project: TI_J7SVB_UFS_ADD-ON-CARD; RoHS: RoHS; Temperature: -25°C+85°C; Tolerance: NA; Voltage: NA; Wattage: NA; Weight: 0.2g; Datasheet: Y:\MIS_DATABASE\DATASHEETS\ICS\MEMORY\THGAF8G8T23BAIL.PDF
C249 C329 = CAP: CAP CERAMIC 0.01uF 50V 10% X7R 0402; Automotive Alternate_mfr_name: TDK; Automotive Alternate_mfr_part_number: CGA2B3X7R1H103K050BB; Chkd/date: MANIRAJA/280319; Crtd /date: MANIRAJA/280319; Custom_Duty: 15%; Customs_HS_Code: 85322990; Direct Alternate_mfr_name: TDK; Direct Alternate_mfr_part_number: C1005X7R1H103K050BE; Distributor_name: DIGIKEY; Distributor_part_number: 490-4516-1-ND; Footprint Path: Y:\MIS_DATABASE\Library\ALTIUM_TOOL\PCB_FOOTPRINTS\Altium_Footprint_Lib.PcbLib; Height: 0.55MM; Library Path: Y:\MIS_DATABASE\Library\ALTIUM_TOOL\SCHEMATICS_PARTS\MS_DISCRETE_Library.schlib; Manufacturer: MURATA; Mfr_name: MURATA; Mfr_part_number: GRM155R71H103KA88D; Mistral Part No: 120009030025-R; Package: 0402; Part_type: CAPACITORS\CERAMIC; Project: G4_SVGA; RoHS: RoHS; Temperature: -55°C+125°C; Tolerance: 10%; Voltage: 50V; Wattage: NA; Weight: 0.65mg; Datasheet: Y:\MIS_DATABASE\DATASHEETS\CAPACITORS\GRM155R71H103KA88D.PDF
C304 = CAP: CAP CERAMIC 0.1uF 16V 10% X7R AUTO 0402; Automotive Alternate_mfr_name: TDK; Automotive Alternate_mfr_part_number: CGA2B1X7R1C104K050BC; Chkd/date: NAVEED/021014; Crtd /date: VASANTHA/300514; Custom_Duty: 15%; Customs_HS_Code: 85322990; Direct Alternate_mfr_name: MURATA; Direct Alternate_mfr_part_number: GCM155R71C104JA55D; Distributor_name: DIGIKEY; Distributor_part_number: 490-4759-1-ND; Footprint Path: Y:\MIS_DATABASE\Library\ALTIUM_TOOL\PCB_FOOTPRINTS\Altium_Footprint_Lib.PcbLib; Height: 0.55MM; Library Path: Y:\MIS_DATABASE\Library\ALTIUM_TOOL\SCHEMATICS_PARTS\MS_DISCRETE_Library.schlib; Manufacturer: MURATA; Mfr_name: MURATA; Mfr_part_number: GCM155R71C104KA55D; Mistral Part No: 120016070006-R; Package: 0402; Part_type: CAPACITORS\CERAMIC; Project: DCMIST_FPGA_CARD; RoHS: RoHS; Temperature: -55°C+125°C; Tolerance: 10%; Voltage: 16V; Wattage: NA; Weight: 6mg; Datasheet: Y:\MIS_DATABASE\DATASHEETS\CAPACITORS\MURATA-GCM-SER.PDF
C1122 = CAP: CAP CERAMIC 0.01uF 50V 10% X7R 0402; Automotive Alternate_mfr_name: TDK; Automotive Alternate_mfr_part_number: CGA2B2X7R1E103K050BA; Chkd/date: MANIRAJA/280319; Crtd /date: MANIRAJA/280319; Custom_Duty: 15%; Customs_HS_Code: 85322990; Direct Alternate_mfr_name: YAGEO AMERICA; Direct Alternate_mfr_part_number: CC0402KRX7R8BB103; Distributor_name: DIGIKEY; Distributor_part_number: 490-4516-1-ND; Footprint Path: Y:\MIS_DATABASE\Library\ALTIUM_TOOL\PCB_FOOTPRINTS\Altium_Footprint_Lib.PcbLib; Height: 0.55MM; Library Path: Y:\MIS_DATABASE\Library\ALTIUM_TOOL\SCHEMATICS_PARTS\MS_DISCRETE_Library.schlib; Manufacturer: MURATA; Mfr_name: MURATA; Mfr_part_number: GRM155R71H103KA88D; Mistral Part No: 120009030025-R; Package: 0402; Part_type: CAPACITORS\CERAMIC; Project: G4_SVGA; RoHS: RoHS; Temperature: -55°C+125°C; Tolerance: 10%; Voltage: 50V; Wattage: NA; Weight: 0.65mg; Datasheet: Y:\MIS_DATABASE\DATASHEETS\CAPACITORS\GRM155R71H103KA88D.PDF
R331 R353 R479 R498 = RESISTOR: RES 10K 1/16W 1% 0402; Chkd/date: VASANTHA/201216; Crtd /date: GEETHA/290506; Custom_Duty: 15%; Customs_HS_Code: 85332119; Distributor_name: DIGIKEY; Distributor_part_number: 311-10.0KLRTR-ND; Footprint Path: Y:\MIS_DATABASE\Library\ALTIUM_TOOL\PCB_FOOTPRINTS\Altium_Footprint_Lib.PcbLib; Height: 0.40MM; Library Path: Y:\MIS_DATABASE\Library\ALTIUM_TOOL\SCHEMATICS_PARTS\MS_DISCRETE_Library.schlib; Manufacturer: YAGEO AMERICA; Mfr_name: YAGEO AMERICA; Mfr_part_number: RC0402FR-0710KL; Mistral Part No: 110015090015-R; Package: 0402; Part_type: RESISTORS\FIXED; Project: VOCERA; RoHS: RoHS; Temperature: -55°C+155°C; Tolerance: 1%; Voltage: NA; Wattage: 1/16W; Weight: 0.65mg; Datasheet: Y:\MIS_DATABASE\DATASHEETS\RESISTORS\RCXXXXL-SER_MAR18.PDF
R336 R358 R472 R499 = RESISTOR: RES 10K 1/16W 1% 0402; Assembly_Instruction: DNI; Chkd/date: VASANTHA/201216; Crtd /date: GEETHA/290506; Custom_Duty: 15%; Customs_HS_Code: 85332119; Distributor_name: DIGIKEY; Distributor_part_number: 311-10.0KLRTR-ND; Footprint Path: Y:\MIS_DATABASE\Library\ALTIUM_TOOL\PCB_FOOTPRINTS\Altium_Footprint_Lib.PcbLib; Height: 0.40MM; Library Path: Y:\MIS_DATABASE\Library\ALTIUM_TOOL\SCHEMATICS_PARTS\MS_DISCRETE_Library.schlib; Manufacturer: YAGEO AMERICA; Mfr_name: YAGEO AMERICA; Mfr_part_number: RC0402FR-0710KL; Mistral Part No: 110015090015-R; Package: 0402; Part_type: RESISTORS\FIXED; Project: VOCERA; RoHS: RoHS; Temperature: -55°C+155°C; Tolerance: 1%; Voltage: NA; Wattage: 1/16W; Weight: 0.65mg; Datasheet: Y:\MIS_DATABASE\DATASHEETS\RESISTORS\RCXXXXL-SER_MAR18.PDF
R456 R463 = RESISTOR: RES 2.2K 1/20W 5% 0201; Chkd/date: MANIRAJA/050517; Crtd /date: MANIRAJA/050517; Custom_Duty: 15%; Customs_HS_Code: 85332119; Distributor_name: DIGIKEY; Distributor_part_number: 311-2.2KNCT-ND; Footprint Path: Y:\MIS_DATABASE\Library\ALTIUM_TOOL\PCB_FOOTPRINTS\Altium_Footprint_Lib.PcbLib; Height: 0.26MM; Library Path: Y:\MIS_DATABASE\Library\ALTIUM_TOOL\SCHEMATICS_PARTS\MS_DISCRETE_Library.schlib; Manufacturer: YAGEO AMERICA; Mfr_name: YAGEO AMERICA; Mfr_part_number: RC0201JR-072K2L; Mistral Part No: 110009030427-R; Package: 0201; Part_type: RESISTORS\FIXED; Project: GOLDEN-I LITE; RoHS: RoHS; Temperature: -55°C+125°C; Tolerance: 5%; Voltage: NA; Wattage: 1/20W; Weight: 0.17mg; Datasheet: Y:\MIS_DATABASE\DATASHEETS\RESISTORS\RCXXXXL-SER_MAR18.PDF
R1055 R1077 R1078 R1095 R1178 R1179 = RESISTOR: RES 10K 1/16W 5% 0402; Assembly_Instruction: DNI; Chkd/date: VASANTHA/061216; Crtd /date: MAZHAR/230805; Custom_Duty: 15%; Customs_HS_Code: 85332119; Distributor_name: DIGIKEY; Distributor_part_number: 311-10KJRCT-ND; Footprint Path: Y:\MIS_DATABASE\Library\ALTIUM_TOOL\PCB_FOOTPRINTS\Altium_Footprint_Lib.PcbLib; Height: 0.40MM; Library Path: Y:\MIS_DATABASE\Library\ALTIUM_TOOL\SCHEMATICS_PARTS\MS_DISCRETE_Library.schlib; Manufacturer: YAGEO AMERICA; Mfr_name: YAGEO AMERICA; Mfr_part_number: RC0402JR-0710KL; Mistral Part No: 110011060021-R; Package: 0402; Part_type: RESISTORS\FIXED; Project: HSE; RoHS: RoHS; Temperature: -55°C+155°C; Tolerance: 5%; Voltage: NA; Wattage: 1/16W; Weight: 0.65mg; Datasheet: Y:\MIS_DATABASE\DATASHEETS\RESISTORS\RCXXXXL-SER_MAR18.PDF
U55 U82 = TMP100NA_3K_SOT23-6: IC TEMPERATURE SENSOR WITH I2C AND SMBUS INTERFACE SOT23-6; Automotive Alternate_mfr_name: TEXAS INSTRUMENTS; Automotive Alternate_mfr_part_number: TMP100AQDBVRQ1; Chkd/date: MANIRAJA/290817; Crtd /date: MANIRAJA/290817; Custom_Duty: 15%; Customs_HS_Code: 85423100; Distributor_name: DIGIKEY; Distributor_part_number: 296-26833-1-ND; Height: 1.45MM; Library Ref: TMP100NA/3K_SOT23-6; Manufacturer: TEXAS INSTRUMENTS; Mfr_name: TEXAS INSTRUMENTS; Mistral Part No: 141017080030-R; Package: SOT23-6; Part_type: ICS\DIGITAL\PERIPHERAL; Project: TI_MAXIE_CPB; RoHS: RoHS; Temperature: -55°C+125°C; Tolerance: NA; Voltage: NA; Wattage: NA; Weight: 120mg; Datasheet: Y:\MIS_DATABASE\DATASHEETS\ICS\DIGITAL\PERIPHERAL\TMP10XX.PDF
U72 = CAT24C256WI-GT3_SOIC8: IC 256K I2C CMOS SERIAL EEPROM SOIC8; Chkd/date: MANIRAJA/130617; Crtd /date: MUDDU/270510; Custom_Duty: 15%; Customs_HS_Code: 85423100; Distributor_name: DIGIKEY; Distributor_part_number: CAT24C256WI-GT3-ND; Height: 1.75MM; Manufacturer: ON SEMICONDUCTOR; Mfr_name: ON SEMICONDUCTOR; Mistral Part No: 141110050004-R; Package: SOIC8; Part_type: ICS\DIGITAL\MEMORY; Project: CENTAURUS; RoHS: RoHS; Temperature: -40°C+85°C; Tolerance: NA; Voltage: NA; Wattage: NA; Weight: 540mg; Datasheet: Y:\MIS_DATABASE\DATASHEETS\ICS\MEMORY\CAT24C256WI.PDF
U73 = CAT24C256WI-GT3_SOIC8: IC 256Kb I2C AUTOMOTIVE SERIAL EEPROM TSSOP8; Chkd/date: ALVY/241121; Crtd /date: TAMILARASU/241121; Custom_Duty: 15%; Customs_HS_Code: 85423100; Distributor_name: DIGIKEY; Distributor_part_number: CAV24C256YE-GT3-ND; Footprint Path: Y:\MIS_DATABASE\Library\ALTIUM_TOOL\PCB_FOOTPRINTS\Altium_Footprint_Lib.PcbLib; Height: 1.20MM; Library Path: Y:\MIS_DATABASE\Library\ALTIUM_TOOL\SCHEMATICS_PARTS\MS_MISCMEMORY_Library.schlib; Manufacturer: ON SEMICONDUCTOR; Mfr_name: ON SEMICONDUCTOR; Mistral Part No: 141121110003-R; Package: TSSOP8; Part_type: ICS\DIGITAL\MEMORY; Project: J7AEP SOM_BRD; RoHS: RoHS; Temperature: -40°C+125°C; Tolerance: NA; Voltage: NA; Wattage: NA; Weight: 158mg; Datasheet: Y:\MIS_DATABASE\DATASHEETS\ICS\MEMORY\CAV24C256XXX.PDF
U78 = SN74LVC2G66DCUR_VSSOP8: IC DUAL BILATERAL ANALOG SWITCH VSSOP8; Chkd/date: MANIRAJA/070319; Crtd /date: ALVY/070319; Custom_Duty: 15%; Customs_HS_Code: 85423100; Distributor_name: DIGIKEY; Distributor_part_number: 296-29056-1-ND; Footprint Path: Y:\MIS_DATABASE\Library\ALTIUM_TOOL\PCB_FOOTPRINTS\Altium_Footprint_Lib.PcbLib; Height: 0.90MM; Library Path: Y:\MIS_DATABASE\Library\ALTIUM_TOOL\SCHEMATICS_PARTS\MS_ANALOG-APPLICATION_Library.schlib; Manufacturer: TEXAS INSTRUMENTS; Mfr_name: TEXAS INSTRUMENTS; Mistral Part No: 140119030001-R; Package: VSSOP8; Part_type: ICS\ANALOG\SWITCH; Project: TI_J7ES_EVM_SOM; RoHS: RoHS; Temperature: -40°C+125°C; Tolerance: NA; Voltage: NA; Wattage: NA; Weight: 20mg; Datasheet: Y:\MIS_DATABASE\DATASHEETS\ICS\ANALOG\SN74LVC2G66-Q1.PDF
U250 = AT24HC04B-TH-B_TSSOP8: IC 1MBIT I2C SERIAL EEPROM TSSOP8; Chkd/date: NAVEED/241114; Crtd /date: VASANTHA/230914; Custom_Duty: 15%; Customs_HS_Code: 85423100; Distributor_name: DIGIKEY; Distributor_part_number: AT24CM01-XHD-TCT-ND; Height: 1.20MM; Manufacturer: ATMEL; Mfr_name: ATMEL; Mfr_part_number: AT24CM01-XHD-T; Mistral Part No: 141114090006-R; Package: TSSOP8; Part_type: ICS\DIGITAL\MEMORY; Project: GALILEO_EVM; RoHS: RoHS; Temperature: -40°C+85°C; Tolerance: NA; Voltage: NA; Wattage: NA; Weight: 158mg; Datasheet: Y:\MIS_DATABASE\DATASHEETS\ICS\MEMORY\AT24CM01.PDF

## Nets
DGND: C107.2 C113.2 C119.2 C149.2 C170.2 C249.2 C289.2 C304.2 C329.2 C600.2 C601.2 C604.2 C605.2 C606.2 C608.2 C609.2 C610.2 C612.2 C613.2 C614.2 C615.2 C616.2 C617.2 C618.2 C619.2 C620.2 C631.2 C632.2 C633.2 C634.2 C635.2 C636.2 C637.2 C638.2 C639.2 C640.2 C641.2 C642.2 C721.2 C769.2 C785.2 C786.2 C788.2 C789.2 C790.2 C802.2 C803.2 C804.2 C807.2 C808.2 C1122.2 J53.6(VSS) J53.10 J53.11 J53.12(CD2) J53.13 J53.14 R331.1 R358.2 R479.1 R498.1 R976.1 R1055.2 R1087.1 R1088.1 R1182.1 R1183.1 U26.B2(VSS) U26.B11(VSS) U26.B12(VSS) U26.C1(VSS) U26.C2(VSS) U26.C3(VSS) U26.C11(VSS) U26.C12(VSS) U26.D3(VSS) U26.D12(VSS) U26.D13(VSS) U26.D14(VSS) U26.E1(VSS) U26.E2(VSS) U26.E3(VSS) U26.E12(VSS) U26.F3(VSS) U26.F12(VSS) U26.F13(VSS) U26.F14(VSS) U26.G1(VSS) U26.G2(VSS) U26.G3(VSS) U26.G10(VSS) U26.G12(VSS) U26.H3(VSS) U26.H5(VSS) U26.H10(VSS) U26.H12(VSS) U26.H13(VSS) U26.H14(VSS) U26.J1(VSS) U26.J2(VSS) U26.J3(VSS) U26.J5(VSS) U26.J12(VSS) U26.K3(VSS) U26.K5(VSS) U26.K12(VSS) U26.K13(VSS) U26.K14(VSS) U26.L1(VSS) U26.L2(VSS) U26.L3(VSS) U26.L12(VSS) U26.M3(VSS) U26.M4(VSS) U26.M5(VSS) U26.M12(VSS) U26.M13(VSS) U26.M14(VSS) U26.N2(VSS) U26.N3(VSS) U26.N4(VSS) U26.N5(VSS) U26.N11(VSS) U26.N12(VSS) U26.P4(VSS) U26.P5(VSS) U26.P11(VSS) U26.P12(VSS) U34.2(GND) U52.A6(VSS) U52.C4(VSSQ) U52.E7(VSS) U52.G5(VSS) U52.H10(VSS) U52.J5(VSS) U52.K8(VSS) U52.N2(VSSQ) U52.N5(VSSQ) U52.P4(VSSQ) U52.P6(VSSQ) U55.2(GND) U72.4(VSS) U73.4(VSS) U78.4(GND) U82.2(GND) U191.4(GND) U197.4(GND) U200.4(GND) U202.4(GND) U250.4(GND) ; also on sheet 11 12 13 14 15 16 17 18 20 21 22 23 24 25 26 27 28 29 30 31 32 33 34 35 36 37 38 39 44 45 46 47 48 49 50 51 52 53 54 55 56 57 58 59 60 61 62 63 64 65 66 67 68 69 70 71 72 73 76 77 78 79 81 82 83 84
VCC1V2_UFS: C635.1 C636.1 C637.1 C638.1 C639.1 C640.1 C641.1 C642.1 FL62.1 U26.A4(VCCQ) U26.A5(VCCQ) U26.B4(VCCQ) U26.B5(VCCQ) U26.C4(VCCQ) U26.C5(VCCQ) U26.E5(VCCQ) U26.F5(VCCQ)
VCC1V8_eMMC: C789.1 C802.1 C803.1 C804.1 R274.1 R278.1 R284.1 R293.1 R299.1 R307.1 R317.1 R322.1 R960.1 R961.1 R966.1 U52.C6(VCCQ) U52.M4(VCCQ) U52.N4(VCCQ) U52.P3(VCCQ) U52.P5(VCCQ)
VCC1V8_UFS: C609.1 C610.1 C612.1 C620.1 C631.1 C632.1 C633.1 C634.1 FL60.1 U26.A6(VCCQ2) U26.A7(VCCQ2) U26.B6(VCCQ2) U26.B7(VCCQ2) U26.C6(VCCQ2) U26.C7(VCCQ2) U26.K6(VCCQ2) U26.K7(VCCQ2)
VCC3V3_eMMC: C786.1 C788.1 C790.1 FL98.2 U52.E6(VCC) U52.F5(VCC) U52.J10(VCC) U52.K9(VCC)
VCC3V3_UFS: C613.1 C614.1 C615.1 C616.1 C617.1 C618.1 C619.1 FL61.1 U26.B8(VCC) U26.B9(VCC) U26.C8(VCC) U26.C9(VCC) U26.E8(VCC) U26.K8(VCC) U26.N8(VCC) U26.N9(VCC) U26.P8(VCC) U26.P9(VCC)
VCC_1V2: C604.1 C605.1 FL62.2 ; also on sheet 61 68
VDD_MMC1: C170.1 C721.1 J53.4(VDD) TP58.1(TP) U34.5(QOD) U34.6(VOUT) U200.1(VCC)
VDD_SD_DV: R916.1 R922.1 R934.1 R936.1 R937.1 TP65.1(TP) ; also on sheet 26 74
VDDI_UFS: C107.1 U26.A9(VDDI)
VDDIM: C807.1 C808.1 U52.C2(VDDIM)
VDDIQ2_UFS: C113.1 U26.A8(VDDIQ2)
VDDIQ_UFS: C119.1 U26.A3(VDDIQ)
BOARDID_EEPROM_A0: R1055.1 R1056.2 U72.1(A0) U73.1(A0)
BOARDID_EEPROM_A1: R1077.2 R1087.2 U72.2(A1) U73.2(A1)
BOARDID_EEPROM_A2: R1078.2 R1088.2 U72.3(A2) U73.3(A2)
BOARDID_EEPROM_WP: R1095.2 U72.7(WP) U73.7(WP) ; also on sheet 30 35
BOOT_EEPROM_A1: R1178.2 R1182.2 U250.2(A1)
BOOT_EEPROM_A2: R1179.2 R1183.2 U250.3(A2)
BOOT_EEPROM_WP: R1151.2 U250.7(WP) ; also on sheet 18
CONN_MMC1_SDCD: J53.9(CD1) R903.2 U191.5(IO2) ; also on sheet 20
EMMC_RSTz: R966.2 U52.K5(RST_N) ; also on sheet 37
GPIO_uSD_PWR_EN: R199.2 U34.3(ON) ; also on sheet 38
MCU_I2C0_SCL: U55.1(SCL) U82.1(SCL) U250.6(SCL) ; also on sheet 18 69
MCU_I2C0_SDA: U55.6(SDA) U82.6(SDA) U250.5(SDA) ; also on sheet 18 69
MMC0_CLK: TP101.1(TP) U52.M6(CLK) ; also on sheet 21
MMC0_CMD: R961.2 TP291.1(TP) U52.M5(CMD) ; also on sheet 21
MMC0_DAT0: R307.2 TP94.1(TP) U52.A3(DAT0) ; also on sheet 21
MMC0_DAT1: R293.2 TP83.1(TP) U52.A4(DAT1) ; also on sheet 21
MMC0_DAT2: R278.2 TP79.1(TP) U52.A5(DAT2) ; also on sheet 21
MMC0_DAT3: R322.2 TP100.1(TP) U52.B2(DAT3) ; also on sheet 21
MMC0_DAT4: R317.2 TP97.1(TP) U52.B3(DAT4) ; also on sheet 21
MMC0_DAT5: R299.2 TP87.1(TP) U52.B4(DAT5) ; also on sheet 21
MMC0_DAT6: R284.2 TP80.1(TP) U52.B5(DAT6) ; also on sheet 21
MMC0_DAT7: R274.2 TP76.1(TP) U52.B6(DAT7) ; also on sheet 21
MMC0_DS: R967.1 R976.2 ; also on sheet 21
MMC0_DS_R: R967.2 TP292.1(TP) U52.H5(DS)
MMC1_CLK: J53.5(CLK) U200.5(IO2) ; also on sheet 21
MMC1_CMD: J53.3(CMD) R934.2 U200.3(IO1) ; also on sheet 21
MMC1_DAT0: J53.7(DAT0) R922.2 U197.3(IO1) ; also on sheet 21
MMC1_DAT1: J53.8(DAT1) R916.2 U197.5(IO2) ; also on sheet 21
MMC1_DAT2: J53.1(DAT2) R937.2 U202.3(IO1) ; also on sheet 21
MMC1_DAT3: J53.2(CD/DAT3) R936.2 U202.5(IO2) ; also on sheet 21
SOC_PORZ_OUT: R462.1 ; also on sheet 18 30 32 37 51 56 59 60 62 69
SOC_WKUP_I2C0_SCL: U78.1(1A) ; also on sheet 18 23
SOC_WKUP_I2C0_SDA: U78.5(2A) ; also on sheet 18 23
TMP1_ADD0: R498.2 R499.2 U82.5(ADD0)
TMP1_ADD1: R472.2 R479.2 U82.3(ADD1)
TMP2_ADD0: R353.2 R358.1 U55.5(ADD0)
TMP2_ADD1: R331.2 R336.2 U55.3(ADD1)
UFS0_REF_CLK: U26.H1(REF_CLK) U59.AJ5(UFS0_REF_CLK)
UFS0_RST#: U26.H2(RESET_N) U59.AJ7(UFS0_RSTN)
UFS0_RX0_N: U26.K1(DOUT0_C) U59.AK5(UFS0_RX_DN0)
UFS0_RX0_P: U26.K2(DOUT0_T) U59.AK6(UFS0_RX_DP0)
UFS0_RX1_N: U26.M1(DOUT1_C) U59.AL4(UFS0_RX_DN1)
UFS0_RX1_P: U26.M2(DOUT1_T) U59.AL5(UFS0_RX_DP1)
UFS0_TX0_N: U26.F2(DIN0_C) U59.AN2(UFS0_TX_DN0)
UFS0_TX0_P: U26.F1(DIN0_T) U59.AN3(UFS0_TX_DP0)
UFS0_TX1_N: U26.D2(DIN1_C) U59.AM3(UFS0_TX_DN1)
UFS0_TX1_P: U26.D1(DIN1_T) U59.AM4(UFS0_TX_DP1)
VSYS_3V3: C149.1 U34.1(VIN) ; also on sheet 22 23 35 36 47 49 62 63 65 66 67 68 69 73 75 76 77 78 79
VSYS_IO_1V8: C600.1 C601.1 C785.1 FL60.2 R960.2 ; also on sheet 30 32 33 34 37 38 61 65 75
VSYS_IO_3V3: C289.1 C606.1 C608.1 C769.1 FL61.2 FL98.1 R199.1 R456.2 R463.2 R903.1 R1056.1 R1077.1 R1078.1 R1095.1 U72.8(VCC) U73.8(VCC) ; also on sheet 18 20 22 24 29 30 31 32 33 35 36 37 38 45 46 48 50 51 53 56 57 58 59 60 61 65 66 68 75 81 82
VSYS_MCUIO_3V3: C249.1 C304.1 C329.1 C1122.1 R336.1 R353.1 R472.1 R499.1 R1151.1 R1178.1 R1179.1 U55.4(V+) U78.8(VCC) U82.4(V+) U250.8(VCC) ; also on sheet 16 17 18 21 22 23 35 36 44 48 49 55 62 65 68 75
WKUP_I2C0_SCL: R456.1 U72.6(SCL) U73.6(SCL) U78.2(1B) ; also on sheet 30
WKUP_I2C0_SDA: R463.1 U72.5(SDA) U73.5(SDA) U78.6(2B) ; also on sheet 30
N33102148: R462.2 U78.3(2C) U78.7(1C)

Not connected (* = marked no-connect by the designer): U26 A1(NC1)* A2(NC2)* A10(CPOUT1)* A11(C-)* A12(C+)* A13(NC3)* A14(NC4)* B1(NC5)* B3(RFU1)* B10(CPOUT2)* B13(RFU2)* B14(NC6)* C10(RFU3)* C13(RFU4)* C14(RFU5)* D4(NC7)* E6(VSF1)* E7(VSF2)* E9(VSF3)* E10(VSF4)* E13(RFU6)* E14(RFU7)* F10(VSF5)* G5(VSF6)* G13(RFU8)* G14(RFU9)* J10(VSF7)* J13(RFU10)* J14(RFU11)* K9(NC8)* K10(VSF8)* L13(RFU12)* L14(RFU13)* M6(RFU14)* M7(RFU15)* M8(NC9)* M9(NC10)* M10(RFU16)* M11(NC11)* N1(NC12)* N6(RFU17)* N7(RFU18)* N10(RFU19)* N13(RFU20)* N14(NC13)* P1(NC14)* P2(NC15)* P3(RFU21)* P6(RFU22)* P7(RFU23)* P10(VSF9)* P13(NC16)* P14(NC17)*; U34 4(CT)*; U52 A1(NC1)* A2(NC2)* A7(RFU1)* A8(NC3)* A9(NC4)* A10(NC5)* A11(NC6)* A12(NC7)* A13(NC8)* A14(NC9)* B1(NC10)* B7(NC11)* B8(NC12)* B9(NC13)* B10(NC14)* B11(NC15)* B12(NC16)* B13(NC17)* B14(NC18)* C1(NC19)* C3(NC20)* C5(NC21)* C7(NC22)* C8(NC23)* C9(NC24)* C10(NC25)* C11(NC26)* C12(NC27)* C13(NC28)* C14(NC29)* D1(NC30)* D2(NC31)* D3(NC32)* D4(NC33)* D12(NC34)* D13(NC35)* D14(NC36)* E1(NC37)* E2(NC38)* E3(NC39)* E5(RFU2)* E8(VSF1)* E9(VSF2)* E10(VSF3)* E12(NC40)* E13(NC41)* E14(NC42)* F1(NC43)* F2(NC44)* F3(NC45)* F10(VSF4)* F12(NC46)* F13(NC47)* F14(NC48)* G1(NC49)* G2(NC50)* G3(NC51)* G10(VSF5)* G12(NC52)* G13(NC53)* G14(NC54)* H1(NC55)* H2(NC56)* H3(NC57)* H12(NC58)* H13(NC59)* H14(NC60)* J1(NC61)* J2(NC62)* J3(NC63)* J12(NC64)* J13(NC65)* J14(NC66)* K1(NC67)* K2(NC68)* K3(NC69)* K6(RFU3)* K7(RFU4)* K10(VSF6)* K12(NC70)* K13(NC71)* K14(NC72)* L1(NC73)* L2(NC74)* L3(NC75)* L12(NC76)* L13(NC77)* L14(NC78)* M1(NC79)* M2(NC80)* M3(NC81)* M7(NC82)* M8(NC83)* M9(NC84)* M10(NC85)* M11(NC86)* M12(NC87)* M13(NC88)* M14(NC89)* N1(NC90)* N3(NC91)* N6(NC92)* N7(NC93)* N8(NC94)* N9(NC95)* N10(NC96)* N11(NC97)* N12(NC98)* N13(NC99)* N14(NC100)* P1(NC101)* P2(NC102)* P7(NC103)* P8(NC104)* P9(NC105)* P10(VSF7)* P11(NC106)* P12(NC107)* P13(NC108)* P14(NC109)*; U191 1(VCC)* 2(NC)* 3(IO1)*; U197 1(VCC)* 2(NC)*; U200 2(NC)*; U202 1(VCC)* 2(NC)*; U250 1(NC)*

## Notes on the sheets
sheet 40
- Micro SD CARD INTERFACE
- Load Switch
- From IO Expander
- VDD_SD_DV power is from LDO
- Silkscreen:"uSD CONN"
- Silk: uSD CARD CONN
- Place near SD Card Connector
sheet 41
- eMMC FLASH
- Via Probe Test Points
- Place Near eMMC side
sheet 42
- UFS FLASH
- 100 E
- 100 E
- 100 E
- 100 E
sheet 43
- BOOT EEPROM
- EEPROM Address - 0x50,0x51
- BOARD ID EEPROM
- I2C for BOARD ID EEPROMs
- Dual Footprint support for Board ID EEPROM
- EEPROM Address - 0x50
- Note:logic used to isolate I2C bus from remainder of
  system when operating in MCU-only mode.
- TEMPERATURE SENSORS
- (TI EVM Only)
- I2C ADDRESS: 0x48
- I2C ADDRESS: 0x49
- NOTE: PLACE TEMP SENSOR CLOSE TO Power Section
- NOTE: PLACE TEMP SENSOR CLOSE TO SOC
